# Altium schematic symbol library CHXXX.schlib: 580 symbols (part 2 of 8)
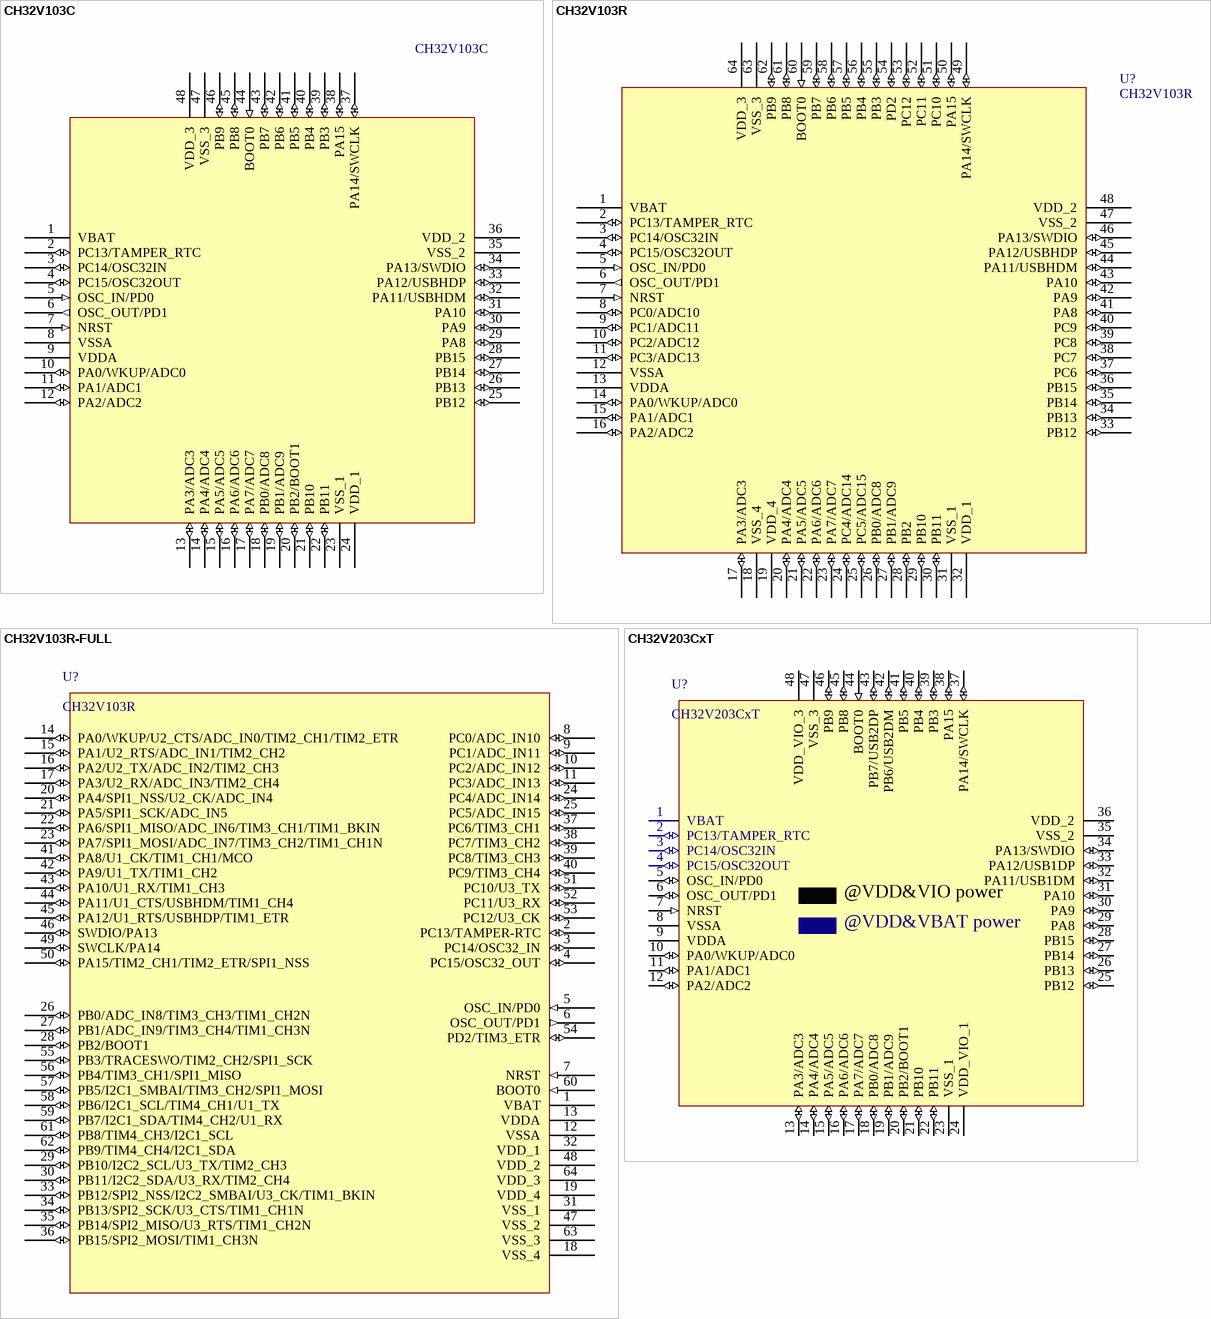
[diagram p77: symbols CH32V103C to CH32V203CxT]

## CH32V103C
designator U?
RISC-V MCU with USB device & USB host & ADC & Touch Key
footprint LQFP48 (Footprint not found)
footprint QFN48_7X7 (Footprint not found)
pins: 1 VBAT (power), 2 PC13/TAMPER_RTC (io), 3 PC14/OSC32IN (io), 4 PC15/OSC32OUT (io), 5 OSC_IN/PD0 (in), 6 OSC_OUT/PD1 (out), 7 NRST (in), 8 VSSA, 9 VDDA, 10 PA0/WKUP/ADC0 (io), 11 PA1/ADC1 (io), 12 PA2/ADC2 (io), 13 PA3/ADC3 (io), 14 PA4/ADC4 (io), 15 PA5/ADC5 (io), 16 PA6/ADC6 (io), 17 PA7/ADC7 (io), 18 PB0/ADC8 (io), 19 PB1/ADC9 (io), 20 PB2/BOOT1 (io), 21 PB10 (io), 22 PB11 (io), 23 VSS_1, 24 VDD_1, 25 PB12 (io), 26 PB13 (io), 27 PB14 (io), 28 PB15 (io), 29 PA8 (io), 30 PA9 (io), 31 PA10 (io), 32 PA11/USBHDM (io), 33 PA12/USBHDP (io), 34 PA13/SWDIO (io), 35 VSS_2, 36 VDD_2, 37 PA14/SWCLK (io), 38 PA15 (io), 39 PB3 (io), 40 PB4 (io), 41 PB5 (io), 42 PB6 (io), 43 PB7 (io), 44 BOOT0 (in), 45 PB8 (io), 46 PB9 (io), 47 VSS_3, 48 VDD_3

## CH32V103R
designator U?
RISC-V MCU with USB device & USB host & ADC & Touch Key
footprint LQFP64M_10X10
pins: 1 VBAT (power), 2 PC13/TAMPER_RTC (io), 3 PC14/OSC32IN (io), 4 PC15/OSC32OUT (io), 5 OSC_IN/PD0 (in), 6 OSC_OUT/PD1 (out), 7 NRST (in), 8 PC0/ADC10 (io), 9 PC1/ADC11 (io), 10 PC2/ADC12 (io), 11 PC3/ADC13 (io), 12 VSSA (power), 13 VDDA (power), 14 PA0/WKUP/ADC0 (io), 15 PA1/ADC1 (io), 16 PA2/ADC2 (io), 17 PA3/ADC3 (io), 18 VSS_4 (power), 19 VDD_4 (power), 20 PA4/ADC4 (io), 21 PA5/ADC5 (io), 22 PA6/ADC6 (io), 23 PA7/ADC7 (io), 24 PC4/ADC14 (io), 25 PC5/ADC15 (io), 26 PB0/ADC8 (io), 27 PB1/ADC9 (io), 28 PB2 (io), 29 PB10 (io), 30 PB11 (io), 31 VSS_1 (power), 32 VDD_1 (power), 33 PB12 (io), 34 PB13 (io), 35 PB14 (io), 36 PB15 (io), 37 PC6 (io), 38 PC7 (io), 39 PC8 (io), 40 PC9 (io), 41 PA8 (io), 42 PA9 (io), 43 PA10 (io), 44 PA11/USBHDM (io), 45 PA12/USBHDP (io), 46 PA13/SWDIO (io), 47 VSS_2 (power), 48 VDD_2 (power), 49 PA14/SWCLK (io), 50 PA15 (io), 51 PC10 (io), 52 PC11 (io), 53 PC12 (io), 54 PD2 (io), 55 PB3 (io), 56 PB4 (io), 57 PB5 (io), 58 PB6 (io), 59 PB7 (io), 60 BOOT0 (in), 61 PB8 (io), 62 PB9 (io), 63 VSS_3 (power), 64 VDD_3 (power)

## CH32V103R-FULL
designator U?, comment CH32V103R
RISC-V MCU with USB device & USB host & ADC & Touch Key
footprint LQFP64M_10X10 (Footprint not found)
pins: 1 VBAT (power), 2 PC13/TAMPER-RTC (io), 3 PC14/OSC32_IN (io), 4 PC15/OSC32_OUT (io), 5 OSC_IN/PD0 (in), 6 OSC_OUT/PD1 (out), 7 NRST (in), 8 PC0/ADC_IN10 (io), 9 PC1/ADC_IN11 (io), 10 PC2/ADC_IN12 (io), 11 PC3/ADC_IN13 (io), 12 VSSA (power), 13 VDDA (power), 14 PA0/WKUP/U2_CTS/ADC_IN0/TIM2_CH1/TIM2_ETR (io), 15 PA1/U2_RTS/ADC_IN1/TIM2_CH2 (io), 16 PA2/U2_TX/ADC_IN2/TIM2_CH3 (io), 17 PA3/U2_RX/ADC_IN3/TIM2_CH4 (io), 18 VSS_4 (power), 19 VDD_4 (power), 20 PA4/SPI1_NSS/U2_CK/ADC_IN4 (io), 21 PA5/SPI1_SCK/ADC_IN5 (io), 22 PA6/SPI1_MISO/ADC_IN6/TIM3_CH1/TIM1_BKIN (io), 23 PA7/SPI1_MOSI/ADC_IN7/TIM3_CH2/TIM1_CH1N (io), 24 PC4/ADC_IN14 (io), 25 PC5/ADC_IN15 (io), 26 PB0/ADC_IN8/TIM3_CH3/TIM1_CH2N (io), 27 PB1/ADC_IN9/TIM3_CH4/TIM1_CH3N (io), 28 PB2/BOOT1 (io), 29 PB10/I2C2_SCL/U3_TX/TIM2_CH3 (io), 30 PB11/I2C2_SDA/U3_RX/TIM2_CH4 (io), 31 VSS_1 (power), 32 VDD_1 (power), 33 PB12/SPI2_NSS/I2C2_SMBAI/U3_CK/TIM1_BKIN (io), 34 PB13/SPI2_SCK/U3_CTS/TIM1_CH1N  (io), 35 PB14/SPI2_MISO/U3_RTS/TIM1_CH2N (io), 36 PB15/SPI2_MOSI/TIM1_CH3N (io), 37 PC6/TIM3_CH1 (io), 38 PC7/TIM3_CH2 (io), 39 PC8/TIM3_CH3 (io), 40 PC9/TIM3_CH4 (io), 41 PA8/U1_CK/TIM1_CH1/MCO (io), 42 PA9/U1_TX/TIM1_CH2 (io), 43 PA10/U1_RX/TIM1_CH3 (io), 44 PA11/U1_CTS/USBHDM/TIM1_CH4 (io), 45 PA12/U1_RTS/USBHDP/TIM1_ETR (io), 46 SWDIO/PA13 (io), 47 VSS_2 (power), 48 VDD_2 (power), 49 SWCLK/PA14 (io), 50 PA15/TIM2_CH1/TIM2_ETR/SPI1_NSS (io), 51 PC10/U3_TX (io), 52 PC11/U3_RX (io), 53 PC12/U3_CK (io), 54 PD2/TIM3_ETR (io), 55 PB3/TRACESWO/TIM2_CH2/SPI1_SCK (io), 56 PB4/TIM3_CH1/SPI1_MISO (io), 57 PB5/I2C1_SMBAI/TIM3_CH2/SPI1_MOSI (io), 58 PB6/I2C1_SCL/TIM4_CH1/U1_TX (io), 59 PB7/I2C1_SDA/TIM4_CH2/U1_RX (io), 60 BOOT0 (in), 61 PB8/TIM4_CH3/I2C1_SCL (io), 62 PB9/TIM4_CH4/I2C1_SDA (io), 63 VSS_3 (power), 64 VDD_3 (power)

## CH32V203CxT
designator U?
RISC-V LMD-MCU, 144MHz, 2*USB FS, CAN
footprint LQFP48
pins: 1 VBAT (power), 2 PC13/TAMPER_RTC (io), 3 PC14/OSC32IN (io), 4 PC15/OSC32OUT (io), 5 OSC_IN/PD0 (io), 6 OSC_OUT/PD1 (io), 7 NRST (in), 8 VSSA (power), 9 VDDA (power), 10 PA0/WKUP/ADC0 (io), 11 PA1/ADC1 (io), 12 PA2/ADC2 (io), 13 PA3/ADC3 (io), 14 PA4/ADC4 (io), 15 PA5/ADC5 (io), 16 PA6/ADC6 (io), 17 PA7/ADC7 (io), 18 PB0/ADC8 (io), 19 PB1/ADC9 (io), 20 PB2/BOOT1 (io), 21 PB10 (io), 22 PB11 (io), 23 VSS_1 (power), 24 VDD_VIO_1 (power), 25 PB12 (io), 26 PB13 (io), 27 PB14 (io), 28 PB15 (io), 29 PA8 (io), 30 PA9 (io), 31 PA10 (io), 32 PA11/USB1DM (io), 33 PA12/USB1DP (io), 34 PA13/SWDIO (io), 35 VSS_2 (power), 36 VDD_2 (power), 37 PA14/SWCLK (io), 38 PA15 (io), 39 PB3 (io), 40 PB4 (io), 41 PB5 (io), 42 PB6/USB2DM (io), 43 PB7/USB2DP (io), 44 BOOT0 (in), 45 PB8 (io), 46 PB9 (io), 47 VSS_3 (power), 48 VDD_VIO_3 (power)

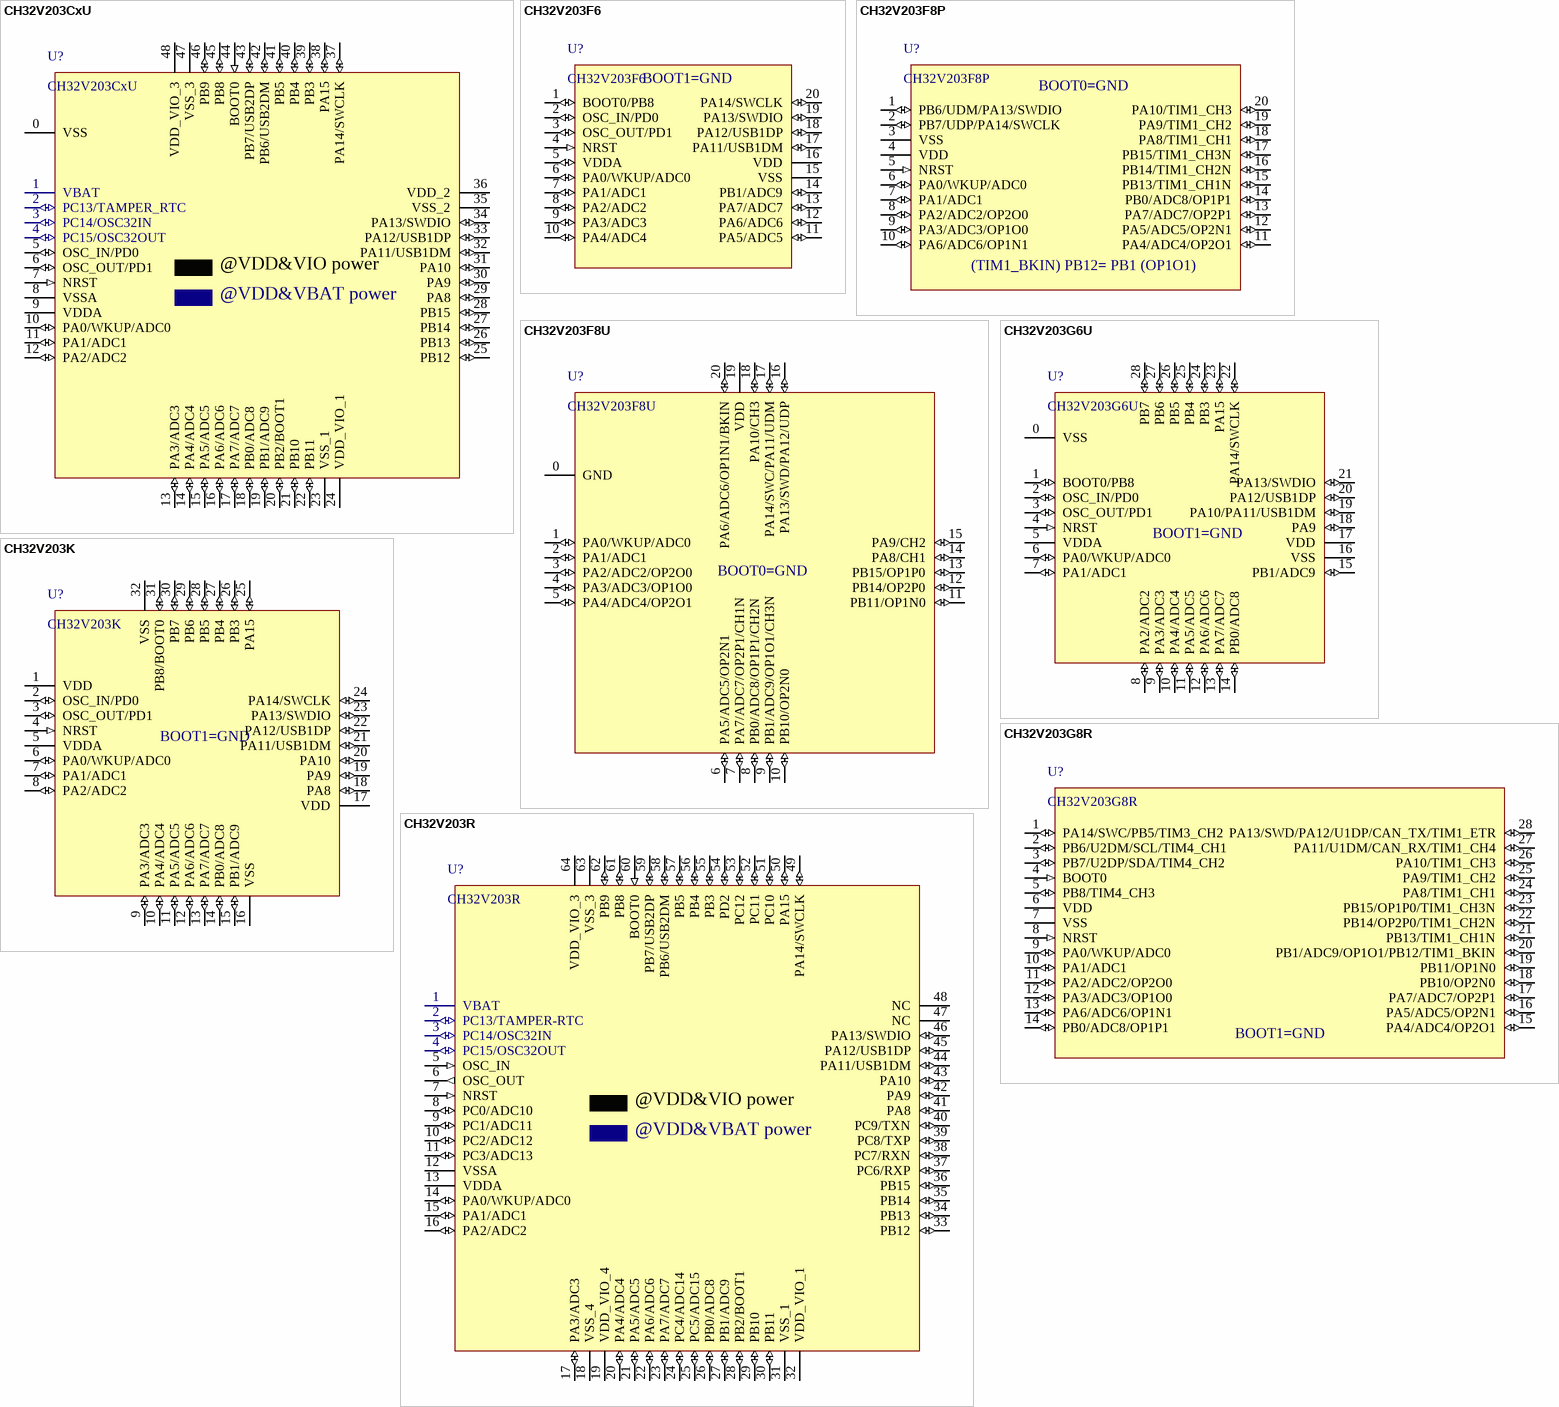
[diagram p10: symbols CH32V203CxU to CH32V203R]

## CH32V203CxU
designator U?
RISC-V LMD-MCU, 144MHz, 2*USB FS, CAN
footprint QFN48_7X7 (Footprint not found)
pins: 0 VSS (power), 1 VBAT (power), 2 PC13/TAMPER_RTC (io), 3 PC14/OSC32IN (io), 4 PC15/OSC32OUT (io), 5 OSC_IN/PD0 (io), 6 OSC_OUT/PD1 (io), 7 NRST (in), 8 VSSA (power), 9 VDDA (power), 10 PA0/WKUP/ADC0 (io), 11 PA1/ADC1 (io), 12 PA2/ADC2 (io), 13 PA3/ADC3 (io), 14 PA4/ADC4 (io), 15 PA5/ADC5 (io), 16 PA6/ADC6 (io), 17 PA7/ADC7 (io), 18 PB0/ADC8 (io), 19 PB1/ADC9 (io), 20 PB2/BOOT1 (io), 21 PB10 (io), 22 PB11 (io), 23 VSS_1 (power), 24 VDD_VIO_1 (power), 25 PB12 (io), 26 PB13 (io), 27 PB14 (io), 28 PB15 (io), 29 PA8 (io), 30 PA9 (io), 31 PA10 (io), 32 PA11/USB1DM (io), 33 PA12/USB1DP (io), 34 PA13/SWDIO (io), 35 VSS_2 (power), 36 VDD_2 (power), 37 PA14/SWCLK (io), 38 PA15 (io), 39 PB3 (io), 40 PB4 (io), 41 PB5 (io), 42 PB6/USB2DM (io), 43 PB7/USB2DP (io), 44 BOOT0 (in), 45 PB8 (io), 46 PB9 (io), 47 VSS_3 (power), 48 VDD_VIO_3 (power)

## CH32V203F6
designator U?
RISC-V LMD-MCU, 144MHz, USB FS, CAN, Mul-ADC,OPA
footprint TSSOP20
pins: 1 BOOT0/PB8 (io), 2 OSC_IN/PD0 (io), 3 OSC_OUT/PD1 (io), 4 NRST (in), 5 VDDA (io), 6 PA0/WKUP/ADC0 (io), 7 PA1/ADC1 (io), 8 PA2/ADC2 (io), 9 PA3/ADC3 (io), 10 PA4/ADC4 (io), 11 PA5/ADC5 (io), 12 PA6/ADC6 (io), 13 PA7/ADC7 (io), 14 PB1/ADC9 (io), 15 VSS (power), 16 VDD (power), 17 PA11/USB1DM (io), 18 PA12/USB1DP (io), 19 PA13/SWDIO (io), 20 PA14/SWCLK (io)

## CH32V203F8P
designator U?
RISC-V LMD-MCU, 144MHz, for motor
footprint TSSOP20
pins: 1 PB6/UDM/PA13/SWDIO (io), 2 PB7/UDP/PA14/SWCLK (io), 3 VSS (power), 4 VDD (power), 5 NRST (in), 6 PA0/WKUP/ADC0 (io), 7 PA1/ADC1 (io), 8 PA2/ADC2/OP2O0 (io), 9 PA3/ADC3/OP1O0 (io), 10 PA6/ADC6/OP1N1 (io), 11 PA4/ADC4/OP2O1 (io), 12 PA5/ADC5/OP2N1 (io), 13 PA7/ADC7/OP2P1 (io), 14 PB0/ADC8/OP1P1 (io), 15 PB13/TIM1_CH1N (io), 16 PB14/TIM1_CH2N (io), 17 PB15/TIM1_CH3N (io), 18 PA8/TIM1_CH1 (io), 19 PA9/TIM1_CH2 (io), 20 PA10/TIM1_CH3 (io)

## CH32V203F8U
designator U?
RISC-V LMD-MCU, 144MHz, for motor & wireless charging
footprint QFN20_3X3
pins: 0 GND (power), 1 PA0/WKUP/ADC0 (io), 2 PA1/ADC1 (io), 3 PA2/ADC2/OP2O0 (io), 4 PA3/ADC3/OP1O0 (io), 5 PA4/ADC4/OP2O1 (io), 6 PA5/ADC5/OP2N1 (io), 7 PA7/ADC7/OP2P1/CH1N (io), 8 PB0/ADC8/OP1P1/CH2N (io), 9 PB1/ADC9/OP1O1/CH3N (io), 10 PB10/OP2N0 (io), 11 PB11/OP1N0 (io), 12 PB14/OP2P0 (io), 13 PB15/OP1P0 (io), 14 PA8/CH1 (io), 15 PA9/CH2 (io), 16 PA13/SWD/PA12/UDP (io), 17 PA14/SWC/PA11/UDM (io), 18 PA10/CH3 (io), 19 VDD (power), 20 PA6/ADC6/OP1N1/BKIN (io)

## CH32V203G6U
designator U?
RISC-V LMD-MCU, 144MHz, USB FS, CAN, Mul-ADC,OPA
footprint QFN28_4X4
pins: 0 VSS (power), 1 BOOT0/PB8 (io), 2 OSC_IN/PD0 (io), 3 OSC_OUT/PD1 (io), 4 NRST (in), 5 VDDA (power), 6 PA0/WKUP/ADC0 (io), 7 PA1/ADC1 (io), 8 PA2/ADC2 (io), 9 PA3/ADC3 (io), 10 PA4/ADC4 (io), 11 PA5/ADC5 (io), 12 PA6/ADC6 (io), 13 PA7/ADC7 (io), 14 PB0/ADC8 (io), 15 PB1/ADC9 (io), 16 VSS (power), 17 VDD (power), 18 PA9 (io), 19 PA10/PA11/USB1DM (io), 20 PA12/USB1DP (io), 21 PA13/SWDIO (io), 22 PA14/SWCLK (io), 23 PA15 (io), 24 PB3 (io), 25 PB4 (io), 26 PB5 (io), 27 PB6 (io), 28 PB7 (io)

## CH32V203G8R
designator U?
RISC-V LMD-MCU, 144MHz, for motor & wireless charging
footprint QSOP28
pins: 1 PA14/SWC/PB5/TIM3_CH2 (io), 2 PB6/U2DM/SCL/TIM4_CH1 (io), 3 PB7/U2DP/SDA/TIM4_CH2 (io), 4 BOOT0 (in), 5 PB8/TIM4_CH3 (io), 6 VDD (power), 7 VSS (power), 8 NRST (in), 9 PA0/WKUP/ADC0 (io), 10 PA1/ADC1 (io), 11 PA2/ADC2/OP2O0 (io), 12 PA3/ADC3/OP1O0 (io), 13 PA6/ADC6/OP1N1 (io), 14 PB0/ADC8/OP1P1 (io), 15 PA4/ADC4/OP2O1 (io), 16 PA5/ADC5/OP2N1 (io), 17 PA7/ADC7/OP2P1 (io), 18 PB10/OP2N0 (io), 19 PB11/OP1N0 (io), 20 PB1/ADC9/OP1O1/PB12/TIM1_BKIN (io), 21 PB13/TIM1_CH1N (io), 22 PB14/OP2P0/TIM1_CH2N (io), 23 PB15/OP1P0/TIM1_CH3N (io), 24 PA8/TIM1_CH1 (io), 25 PA9/TIM1_CH2 (io), 26 PA10/TIM1_CH3 (io), 27 PA11/U1DM/CAN_RX/TIM1_CH4 (io), 28 PA13/SWD/PA12/U1DP/CAN_TX/TIM1_ETR (io)

## CH32V203K
designator U?
RISC-V LMD-MCU, 144MHz, USB FS, CAN
footprint LQFP32
pins: 1 VDD (power), 2 OSC_IN/PD0 (io), 3 OSC_OUT/PD1 (io), 4 NRST (in), 5 VDDA (power), 6 PA0/WKUP/ADC0 (io), 7 PA1/ADC1 (io), 8 PA2/ADC2 (io), 9 PA3/ADC3 (io), 10 PA4/ADC4 (io), 11 PA5/ADC5 (io), 12 PA6/ADC6 (io), 13 PA7/ADC7 (io), 14 PB0/ADC8 (io), 15 PB1/ADC9 (io), 16 VSS (power), 17 VDD (power), 18 PA8 (io), 19 PA9 (io), 20 PA10 (io), 21 PA11/USB1DM (io), 22 PA12/USB1DP (io), 23 PA13/SWDIO (io), 24 PA14/SWCLK (io), 25 PA15 (io), 26 PB3 (io), 27 PB4 (io), 28 PB5 (io), 29 PB6 (io), 30 PB7 (io), 31 PB8/BOOT0 (io), 32 VSS (power)

## CH32V203R
designator U?
RISC-V HD-MCU, 10M Ethernet, 2*USB, CAN
footprint LQFP64M_10X10
pins: 1 VBAT (power), 2 PC13/TAMPER-RTC (io), 3 PC14/OSC32IN (io), 4 PC15/OSC32OUT (io), 5 OSC_IN (in), 6 OSC_OUT (out), 7 NRST (in), 8 PC0/ADC10 (io), 9 PC1/ADC11 (io), 10 PC2/ADC12 (io), 11 PC3/ADC13 (io), 12 VSSA (power), 13 VDDA (power), 14 PA0/WKUP/ADC0 (io), 15 PA1/ADC1 (io), 16 PA2/ADC2 (io), 17 PA3/ADC3 (io), 18 VSS_4 (power), 19 VDD_VIO_4 (power), 20 PA4/ADC4 (io), 21 PA5/ADC5 (io), 22 PA6/ADC6 (io), 23 PA7/ADC7 (io), 24 PC4/ADC14 (io), 25 PC5/ADC15 (io), 26 PB0/ADC8 (io), 27 PB1/ADC9 (io), 28 PB2/BOOT1 (io), 29 PB10 (io), 30 PB11 (io), 31 VSS_1 (power), 32 VDD_VIO_1 (power), 33 PB12 (io), 34 PB13 (io), 35 PB14 (io), 36 PB15 (io), 37 PC6/RXP (io), 38 PC7/RXN (io), 39 PC8/TXP (io), 40 PC9/TXN (io), 41 PA8 (io), 42 PA9 (io), 43 PA10 (io), 44 PA11/USB1DM (io), 45 PA12/USB1DP (io), 46 PA13/SWDIO (io), 47 NC (power), 48 NC (power), 49 PA14/SWCLK (io), 50 PA15 (io), 51 PC10 (io), 52 PC11 (io), 53 PC12 (io), 54 PD2 (io), 55 PB3 (io), 56 PB4 (io), 57 PB5 (io), 58 PB6/USB2DM (io), 59 PB7/USB2DP (io), 60 BOOT0 (in), 61 PB8 (io), 62 PB9 (io), 63 VSS_3 (power), 64 VDD_VIO_3 (power)

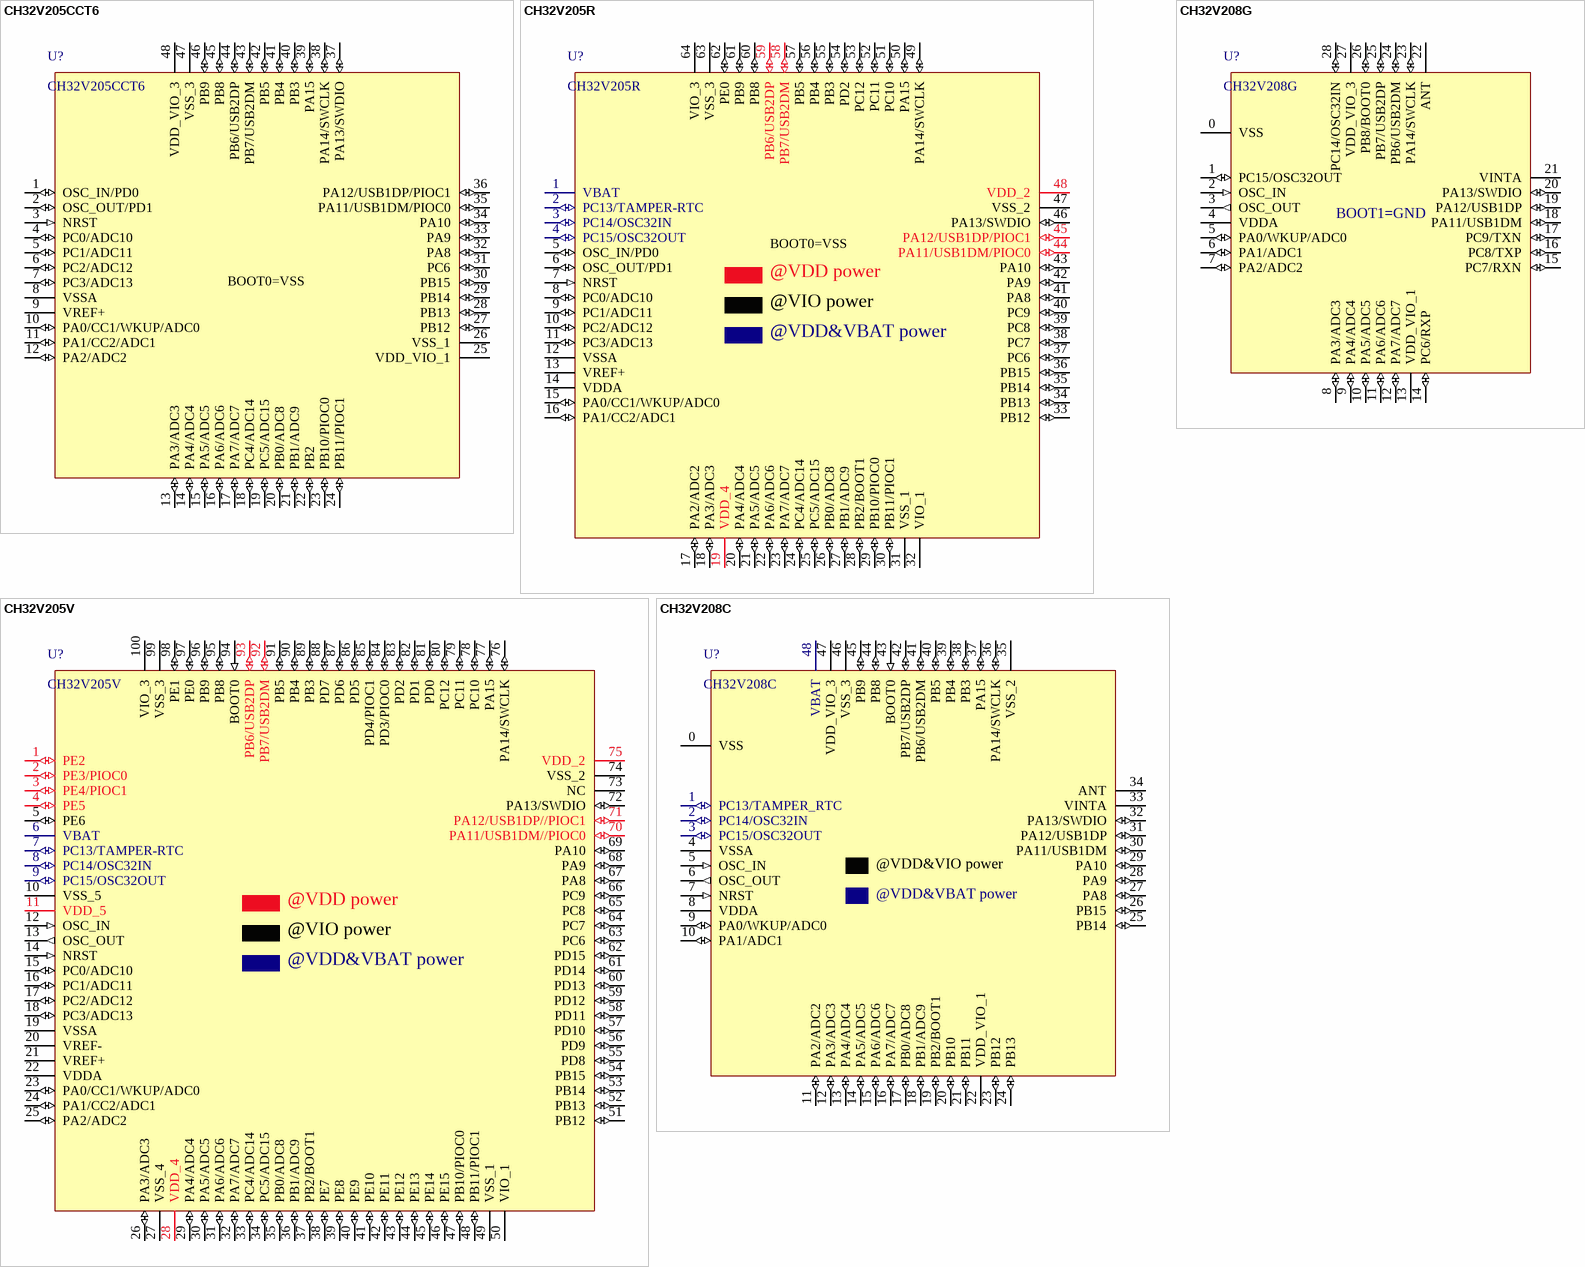
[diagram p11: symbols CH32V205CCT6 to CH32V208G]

## CH32V205CCT6
designator U?
RISC-V MCU, 192MHz, USB_480M, USB FS, PD, PIOC, ADC, TKEY, 2*OPA, 2*CMP
footprint LQFP48
pins: 1 OSC_IN/PD0 (io), 2 OSC_OUT/PD1 (io), 3 NRST (in), 4 PC0/ADC10 (io), 5 PC1/ADC11 (io), 6 PC2/ADC12 (io), 7 PC3/ADC13 (io), 8 VSSA (power), 9 VREF+ (power), 10 PA0/CC1/WKUP/ADC0 (io), 11 PA1/CC2/ADC1 (io), 12 PA2/ADC2 (io), 13 PA3/ADC3 (io), 14 PA4/ADC4 (io), 15 PA5/ADC5 (io), 16 PA6/ADC6 (io), 17 PA7/ADC7 (io), 18 PC4/ADC14 (io), 19 PC5/ADC15 (io), 20 PB0/ADC8 (io), 21 PB1/ADC9 (io), 22 PB2 (io), 23 PB10/PIOC0 (io), 24 PB11/PIOC1 (io), 25 VDD_VIO_1 (power), 26 VSS_1 (power), 27 PB12 (io), 28 PB13 (io), 29 PB14 (io), 30 PB15 (io), 31 PC6 (io), 32 PA8 (io), 33 PA9 (io), 34 PA10 (io), 35 PA11/USB1DM/PIOC0 (io), 36 PA12/USB1DP/PIOC1 (io), 37 PA13/SWDIO (io), 38 PA14/SWCLK (io), 39 PA15 (io), 40 PB3 (io), 41 PB4 (io), 42 PB5 (io), 43 PB7/USB2DM (io), 44 PB6/USB2DP (io), 45 PB8 (io), 46 PB9 (io), 47 VSS_3 (power), 48 VDD_VIO_3 (power)

## CH32V205R
designator U?
RISC-V MCU, 192MHz, USB_480M, USB FS, PD, PIOC, ADC, TKEY, 2*OPA, 2*CMP
footprint LQFP64_7X7 (Footprint not found)
pins: 1 VBAT (power), 2 PC13/TAMPER-RTC (io), 3 PC14/OSC32IN (io), 4 PC15/OSC32OUT (io), 5 OSC_IN/PD0 (io), 6 OSC_OUT/PD1 (io), 7 NRST (in), 8 PC0/ADC10 (io), 9 PC1/ADC11 (io), 10 PC2/ADC12 (io), 11 PC3/ADC13 (io), 12 VSSA (power), 13 VREF+ (power), 14 VDDA (power), 15 PA0/CC1/WKUP/ADC0 (io), 16 PA1/CC2/ADC1 (io), 17 PA2/ADC2 (io), 18 PA3/ADC3 (io), 19 VDD_4 (power), 20 PA4/ADC4 (io), 21 PA5/ADC5 (io), 22 PA6/ADC6 (io), 23 PA7/ADC7 (io), 24 PC4/ADC14 (io), 25 PC5/ADC15 (io), 26 PB0/ADC8 (io), 27 PB1/ADC9 (io), 28 PB2/BOOT1 (io), 29 PB10/PIOC0 (io), 30 PB11/PIOC1 (io), 31 VSS_1 (power), 32 VIO_1 (power), 33 PB12 (io), 34 PB13 (io), 35 PB14 (io), 36 PB15 (io), 37 PC6 (io), 38 PC7 (io), 39 PC8 (io), 40 PC9 (io), 41 PA8 (io), 42 PA9 (io), 43 PA10 (io), 44 PA11/USB1DM/PIOC0 (io), 45 PA12/USB1DP/PIOC1 (io), 46 PA13/SWDIO (io), 47 VSS_2 (power), 48 VDD_2 (power), 49 PA14/SWCLK (io), 50 PA15 (io), 51 PC10 (io), 52 PC11 (io), 53 PC12 (io), 54 PD2 (io), 55 PB3 (io), 56 PB4 (io), 57 PB5 (io), 58 PB7/USB2DM (io), 59 PB6/USB2DP (io), 60 PB8 (io), 61 PB9 (io), 62 PE0 (io), 63 VSS_3 (power), 64 VIO_3 (power)

## CH32V205V
designator U?
RISC-V MCU, 192MHz, USB_480M, USB FS, PD, PIOC, ADC, TKEY, 2*OPA, 2*CMP
footprint LQFP100
pins: 1 PE2 (io), 2 PE3/PIOC0 (io), 3 PE4/PIOC1 (io), 4 PE5 (io), 5 PE6 (io), 6 VBAT (power), 7 PC13/TAMPER-RTC (io), 8 PC14/OSC32IN (io), 9 PC15/OSC32OUT (io), 10 VSS_5 (power), 11 VDD_5 (power), 12 OSC_IN (in), 13 OSC_OUT (out), 14 NRST (in), 15 PC0/ADC10 (io), 16 PC1/ADC11 (io), 17 PC2/ADC12 (io), 18 PC3/ADC13 (io), 19 VSSA (power), 20 VREF- (power), 21 VREF+ (power), 22 VDDA (power), 23 PA0/CC1/WKUP/ADC0 (io), 24 PA1/CC2/ADC1 (io), 25 PA2/ADC2 (io), 26 PA3/ADC3 (io), 27 VSS_4 (power), 28 VDD_4 (power), 29 PA4/ADC4 (io), 30 PA5/ADC5 (io), 31 PA6/ADC6 (io), 32 PA7/ADC7 (io), 33 PC4/ADC14 (io), 34 PC5/ADC15 (io), 35 PB0/ADC8 (io), 36 PB1/ADC9 (io), 37 PB2/BOOT1 (io), 38 PE7 (io), 39 PE8 (io), 40 PE9 (io), 41 PE10 (io), 42 PE11 (io), 43 PE12 (io), 44 PE13 (io), 45 PE14 (io), 46 PE15 (io), 47 PB10/PIOC0 (io), 48 PB11/PIOC1 (io), 49 VSS_1 (power), 50 VIO_1 (power), 51 PB12 (io), 52 PB13 (io), 53 PB14 (io), 54 PB15 (io), 55 PD8 (io), 56 PD9 (io), 57 PD10 (io), 58 PD11 (io), 59 PD12 (io), 60 PD13 (io), 61 PD14 (io), 62 PD15 (io), 63 PC6 (io), 64 PC7 (io), 65 PC8 (io), 66 PC9 (io), 67 PA8 (io), 68 PA9 (io), 69 PA10 (io), 70 PA11/USB1DM//PIOC0 (io), 71 PA12/USB1DP//PIOC1 (io), 72 PA13/SWDIO (io), 73 NC (hiz), 74 VSS_2 (power), 75 VDD_2 (power), 76 PA14/SWCLK (io), 77 PA15 (io), 78 PC10 (io), 79 PC11 (io), 80 PC12 (io), 81 PD0 (io), 82 PD1 (io), 83 PD2 (io), 84 PD3/PIOC0 (io), 85 PD4/PIOC1 (io), 86 PD5 (io), 87 PD6 (io), 88 PD7 (io), 89 PB3 (io), 90 PB4 (io), 91 PB5 (io), 92 PB7/USB2DM (io), 93 PB6/USB2DP (io), 94 BOOT0 (in), 95 PB8 (io), 96 PB9 (io), 97 PE0 (io), 98 PE1 (io), 99 VSS_3 (power), 100 VIO_3 (power)

## CH32V208C
designator U?
RISC-V BLE5.3 MCU, 10M Ethernet, 2*USB, CAN
footprint QFN48_5X5
pins: 0 VSS (power), 1 PC13/TAMPER_RTC (io), 2 PC14/OSC32IN (io), 3 PC15/OSC32OUT (io), 4 VSSA (power), 5 OSC_IN (in), 6 OSC_OUT (out), 7 NRST (in), 8 VDDA (power), 9 PA0/WKUP/ADC0 (io), 10 PA1/ADC1 (io), 11 PA2/ADC2 (io), 12 PA3/ADC3 (io), 13 PA4/ADC4 (io), 14 PA5/ADC5 (io), 15 PA6/ADC6 (io), 16 PA7/ADC7 (io), 17 PB0/ADC8 (io), 18 PB1/ADC9 (io), 19 PB2/BOOT1 (io), 20 PB10 (io), 21 PB11 (io), 22 VDD_VIO_1 (power), 23 PB12 (io), 24 PB13 (io), 25 PB14 (io), 26 PB15 (io), 27 PA8 (io), 28 PA9 (io), 29 PA10 (io), 30 PA11/USB1DM (io), 31 PA12/USB1DP (io), 32 PA13/SWDIO (io), 33 VINTA (power), 34 ANT (power), 35 VSS_2 (power), 36 PA14/SWCLK (io), 37 PA15 (io), 38 PB3 (io), 39 PB4 (io), 40 PB5 (io), 41 PB6/USB2DM (io), 42 PB7/USB2DP (io), 43 BOOT0 (in), 44 PB8 (io), 45 PB9 (io), 46 VSS_3 (power), 47 VDD_VIO_3 (power), 48 VBAT (power)

## CH32V208G
designator U?
RISC-V BLE5.3 MCU, 10M Ethernet, 2*USB, CAN
footprint QFN28_4X4
pins: 0 VSS (power), 1 PC15/OSC32OUT (io), 2 OSC_IN (in), 3 OSC_OUT (out), 4 VDDA (power), 5 PA0/WKUP/ADC0 (io), 6 PA1/ADC1 (io), 7 PA2/ADC2 (io), 8 PA3/ADC3 (io), 9 PA4/ADC4 (io), 10 PA5/ADC5 (io), 11 PA6/ADC6 (io), 12 PA7/ADC7 (io), 13 VDD_VIO_1 (power), 14 PC6/RXP (io), 15 PC7/RXN (io), 16 PC8/TXP (io), 17 PC9/TXN (io), 18 PA11/USB1DM (io), 19 PA12/USB1DP (io), 20 PA13/SWDIO (io), 21 VINTA (power), 22 ANT (power), 23 PA14/SWCLK (io), 24 PB6/USB2DM (io), 25 PB7/USB2DP (io), 26 PB8/BOOT0 (io), 27 VDD_VIO_3 (power), 28 PC14/OSC32IN (io)

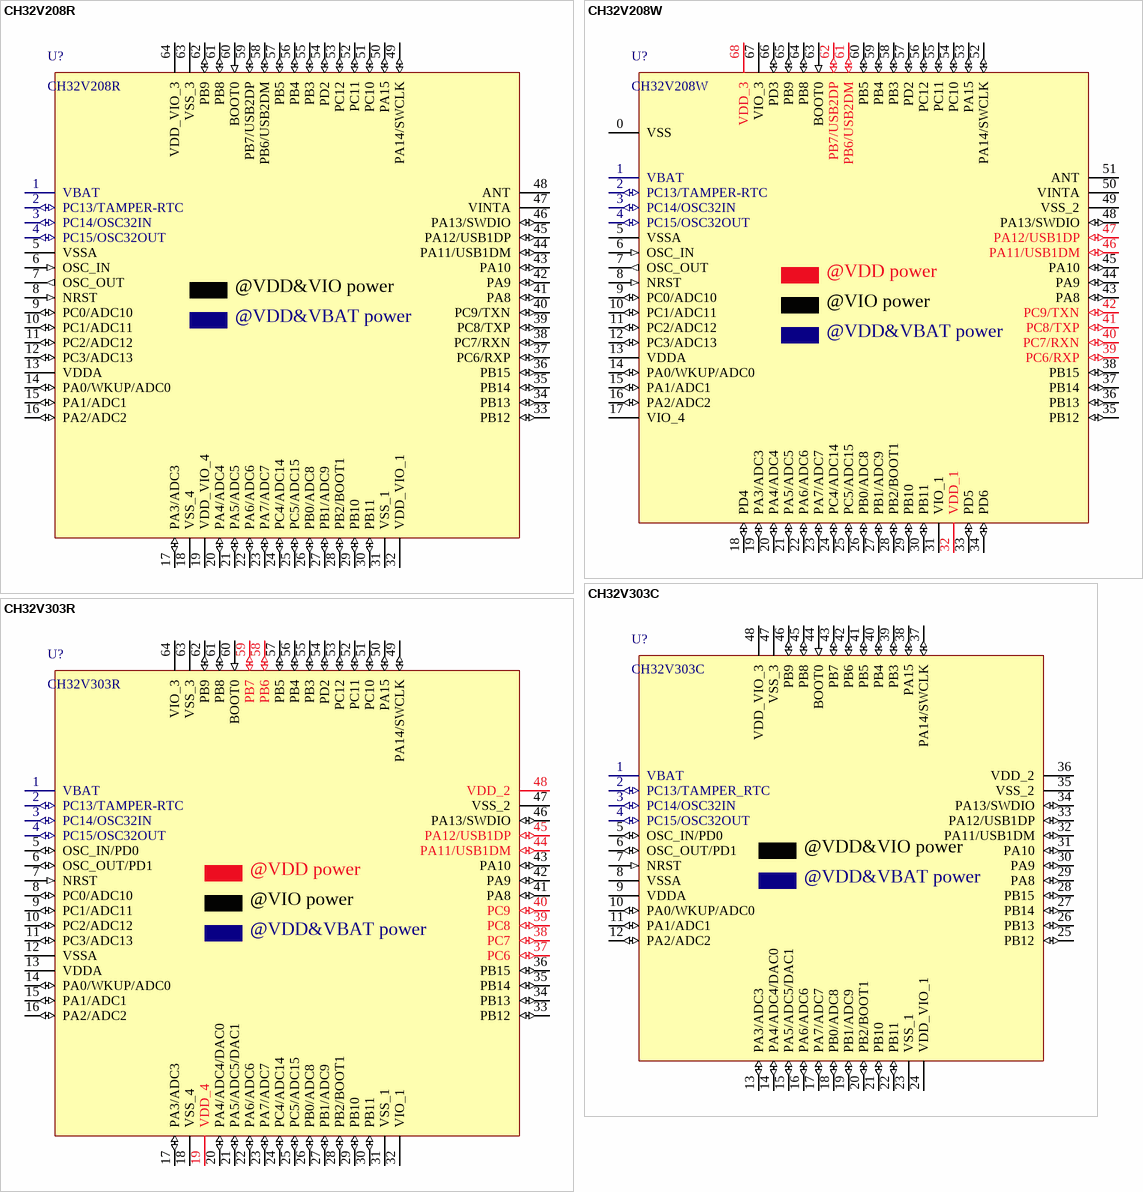
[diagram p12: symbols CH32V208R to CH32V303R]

## CH32V208R
designator U?
RISC-V BLE5.3 MCU, 10M Ethernet, 2*USB, CAN
footprint LQFP64M_10X10
pins: 1 VBAT (power), 2 PC13/TAMPER-RTC (io), 3 PC14/OSC32IN (io), 4 PC15/OSC32OUT (io), 5 VSSA (power), 6 OSC_IN (in), 7 OSC_OUT (out), 8 NRST (in), 9 PC0/ADC10 (io), 10 PC1/ADC11 (io), 11 PC2/ADC12 (io), 12 PC3/ADC13 (io), 13 VDDA (power), 14 PA0/WKUP/ADC0 (io), 15 PA1/ADC1 (io), 16 PA2/ADC2 (io), 17 PA3/ADC3 (io), 18 VSS_4 (power), 19 VDD_VIO_4 (power), 20 PA4/ADC4 (io), 21 PA5/ADC5 (io), 22 PA6/ADC6 (io), 23 PA7/ADC7 (io), 24 PC4/ADC14 (io), 25 PC5/ADC15 (io), 26 PB0/ADC8 (io), 27 PB1/ADC9 (io), 28 PB2/BOOT1 (io), 29 PB10 (io), 30 PB11 (io), 31 VSS_1 (power), 32 VDD_VIO_1 (power), 33 PB12 (io), 34 PB13 (io), 35 PB14 (io), 36 PB15 (io), 37 PC6/RXP (io), 38 PC7/RXN (io), 39 PC8/TXP (io), 40 PC9/TXN (io), 41 PA8 (io), 42 PA9 (io), 43 PA10 (io), 44 PA11/USB1DM (io), 45 PA12/USB1DP (io), 46 PA13/SWDIO (io), 47 VINTA (power), 48 ANT (power), 49 PA14/SWCLK (io), 50 PA15 (io), 51 PC10 (io), 52 PC11 (io), 53 PC12 (io), 54 PD2 (io), 55 PB3 (io), 56 PB4 (io), 57 PB5 (io), 58 PB6/USB2DM (io), 59 PB7/USB2DP (io), 60 BOOT0 (in), 61 PB8 (io), 62 PB9 (io), 63 VSS_3 (power), 64 VDD_VIO_3 (power)

## CH32V208W
designator U?
RISC-V BLE5.3 MCU, 10M Ethernet, 2*USB, CAN
footprint QFN68_8X8
pins: 0 VSS (power), 1 VBAT (power), 2 PC13/TAMPER-RTC (io), 3 PC14/OSC32IN (io), 4 PC15/OSC32OUT (io), 5 VSSA (power), 6 OSC_IN (in), 7 OSC_OUT (out), 8 NRST (in), 9 PC0/ADC10 (io), 10 PC1/ADC11 (io), 11 PC2/ADC12 (io), 12 PC3/ADC13 (io), 13 VDDA (power), 14 PA0/WKUP/ADC0 (io), 15 PA1/ADC1 (io), 16 PA2/ADC2 (io), 17 VIO_4 (power), 18 PD4 (io), 19 PA3/ADC3 (io), 20 PA4/ADC4 (io), 21 PA5/ADC5 (io), 22 PA6/ADC6 (io), 23 PA7/ADC7 (io), 24 PC4/ADC14 (io), 25 PC5/ADC15 (io), 26 PB0/ADC8 (io), 27 PB1/ADC9 (io), 28 PB2/BOOT1 (io), 29 PB10 (io), 30 PB11 (io), 31 VIO_1 (power), 32 VDD_1 (power), 33 PD5 (io), 34 PD6 (io), 35 PB12 (io), 36 PB13 (io), 37 PB14 (io), 38 PB15 (io), 39 PC6/RXP (io), 40 PC7/RXN (io), 41 PC8/TXP (io), 42 PC9/TXN (io), 43 PA8 (io), 44 PA9 (io), 45 PA10 (io), 46 PA11/USB1DM (io), 47 PA12/USB1DP (io), 48 PA13/SWDIO (io), 49 VSS_2 (power), 50 VINTA (power), 51 ANT (power), 52 PA14/SWCLK (io), 53 PA15 (io), 54 PC10 (io), 55 PC11 (io), 56 PC12 (io), 57 PD2 (io), 58 PB3 (io), 59 PB4 (io), 60 PB5 (io), 61 PB6/USB2DM (io), 62 PB7/USB2DP (io), 63 BOOT0 (in), 64 PB8 (io), 65 PB9 (io), 66 PD3 (io), 67 VIO_3 (power), 68 VDD_3 (power)

## CH32V303C
designator U?
RISC-V FPU HD-MCU, 144MHz, 8*UART, 10*Timer, 4*OPA
footprint LQFP48
pins: 1 VBAT (power), 2 PC13/TAMPER_RTC (io), 3 PC14/OSC32IN (io), 4 PC15/OSC32OUT (io), 5 OSC_IN/PD0 (io), 6 OSC_OUT/PD1 (io), 7 NRST (in), 8 VSSA (power), 9 VDDA (power), 10 PA0/WKUP/ADC0 (io), 11 PA1/ADC1 (io), 12 PA2/ADC2 (io), 13 PA3/ADC3 (io), 14 PA4/ADC4/DAC0 (io), 15 PA5/ADC5/DAC1 (io), 16 PA6/ADC6 (io), 17 PA7/ADC7 (io), 18 PB0/ADC8 (io), 19 PB1/ADC9 (io), 20 PB2/BOOT1 (io), 21 PB10 (io), 22 PB11 (io), 23 VSS_1 (power), 24 VDD_VIO_1 (power), 25 PB12 (io), 26 PB13 (io), 27 PB14 (io), 28 PB15 (io), 29 PA8 (io), 30 PA9 (io), 31 PA10 (io), 32 PA11/USB1DM (io), 33 PA12/USB1DP (io), 34 PA13/SWDIO (io), 35 VSS_2 (power), 36 VDD_2 (power), 37 PA14/SWCLK (io), 38 PA15 (io), 39 PB3 (io), 40 PB4 (io), 41 PB5 (io), 42 PB6 (io), 43 PB7 (io), 44 BOOT0 (in), 45 PB8 (io), 46 PB9 (io), 47 VSS_3 (power), 48 VDD_VIO_3 (power)

## CH32V303R
designator U?
RISC-V FPU HD-MCU, 144MHz, 8*UART, 10*Timer, 4*OPA
footprint LQFP64M_10X10
pins: 1 VBAT (power), 2 PC13/TAMPER-RTC (io), 3 PC14/OSC32IN (io), 4 PC15/OSC32OUT (io), 5 OSC_IN/PD0 (io), 6 OSC_OUT/PD1 (io), 7 NRST (in), 8 PC0/ADC10 (io), 9 PC1/ADC11 (io), 10 PC2/ADC12 (io), 11 PC3/ADC13 (io), 12 VSSA (power), 13 VDDA (power), 14 PA0/WKUP/ADC0 (io), 15 PA1/ADC1 (io), 16 PA2/ADC2 (io), 17 PA3/ADC3 (io), 18 VSS_4 (power), 19 VDD_4 (power), 20 PA4/ADC4/DAC0 (io), 21 PA5/ADC5/DAC1 (io), 22 PA6/ADC6 (io), 23 PA7/ADC7 (io), 24 PC4/ADC14 (io), 25 PC5/ADC15 (io), 26 PB0/ADC8 (io), 27 PB1/ADC9 (io), 28 PB2/BOOT1 (io), 29 PB10 (io), 30 PB11 (io), 31 VSS_1 (power), 32 VIO_1 (power), 33 PB12 (io), 34 PB13 (io), 35 PB14 (io), 36 PB15 (io), 37 PC6 (io), 38 PC7 (io), 39 PC8 (io), 40 PC9 (io), 41 PA8 (io), 42 PA9 (io), 43 PA10 (io), 44 PA11/USB1DM (io), 45 PA12/USB1DP (io), 46 PA13/SWDIO (io), 47 VSS_2 (power), 48 VDD_2 (power), 49 PA14/SWCLK (io), 50 PA15 (io), 51 PC10 (io), 52 PC11 (io), 53 PC12 (io), 54 PD2 (io), 55 PB3 (io), 56 PB4 (io), 57 PB5 (io), 58 PB6 (io), 59 PB7 (io), 60 BOOT0 (in), 61 PB8 (io), 62 PB9 (io), 63 VSS_3 (power), 64 VIO_3 (power)

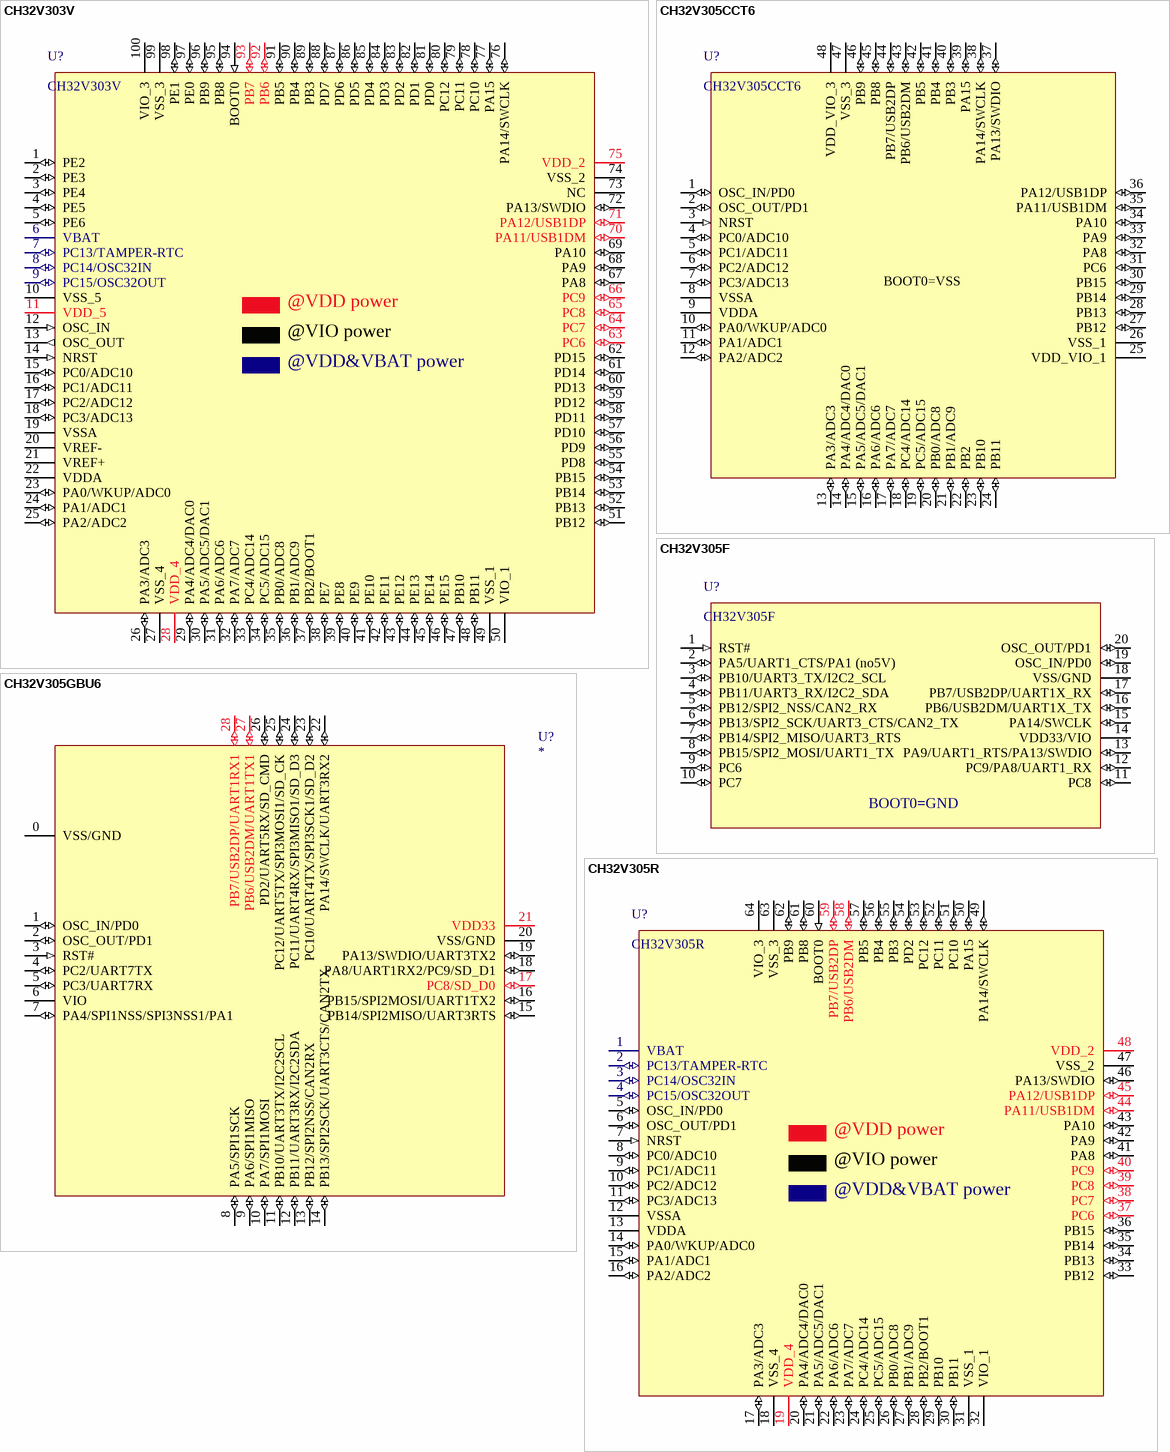
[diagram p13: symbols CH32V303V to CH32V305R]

## CH32V303V
designator U?
RISC-V FPU HD-MCU, 144MHz, 8*UART, 10*Timer, 4*OPA
footprint LQFP100
pins: 1 PE2 (io), 2 PE3 (io), 3 PE4 (io), 4 PE5 (io), 5 PE6 (io), 6 VBAT (power), 7 PC13/TAMPER-RTC (io), 8 PC14/OSC32IN (io), 9 PC15/OSC32OUT (io), 10 VSS_5 (power), 11 VDD_5 (power), 12 OSC_IN (in), 13 OSC_OUT (out), 14 NRST (in), 15 PC0/ADC10 (io), 16 PC1/ADC11 (io), 17 PC2/ADC12 (io), 18 PC3/ADC13 (io), 19 VSSA (power), 20 VREF- (power), 21 VREF+ (power), 22 VDDA (power), 23 PA0/WKUP/ADC0 (io), 24 PA1/ADC1 (io), 25 PA2/ADC2 (io), 26 PA3/ADC3 (io), 27 VSS_4 (power), 28 VDD_4 (power), 29 PA4/ADC4/DAC0 (io), 30 PA5/ADC5/DAC1 (io), 31 PA6/ADC6 (io), 32 PA7/ADC7 (io), 33 PC4/ADC14 (io), 34 PC5/ADC15 (io), 35 PB0/ADC8 (io), 36 PB1/ADC9 (io), 37 PB2/BOOT1 (io), 38 PE7 (io), 39 PE8 (io), 40 PE9 (io), 41 PE10 (io), 42 PE11 (io), 43 PE12 (io), 44 PE13 (io), 45 PE14 (io), 46 PE15 (io), 47 PB10 (io), 48 PB11 (io), 49 VSS_1 (power), 50 VIO_1 (power), 51 PB12 (io), 52 PB13 (io), 53 PB14 (io), 54 PB15 (io), 55 PD8 (io), 56 PD9 (io), 57 PD10 (io), 58 PD11 (io), 59 PD12 (io), 60 PD13 (io), 61 PD14 (io), 62 PD15 (io), 63 PC6 (io), 64 PC7 (io), 65 PC8 (io), 66 PC9 (io), 67 PA8 (io), 68 PA9 (io), 69 PA10 (io), 70 PA11/USB1DM (io), 71 PA12/USB1DP (io), 72 PA13/SWDIO (io), 73 NC (hiz), 74 VSS_2 (power), 75 VDD_2 (power), 76 PA14/SWCLK (io), 77 PA15 (io), 78 PC10 (io), 79 PC11 (io), 80 PC12 (io), 81 PD0 (io), 82 PD1 (io), 83 PD2 (io), 84 PD3 (io), 85 PD4 (io), 86 PD5 (io), 87 PD6 (io), 88 PD7 (io), 89 PB3 (io), 90 PB4 (io), 91 PB5 (io), 92 PB6 (io), 93 PB7 (io), 94 BOOT0 (in), 95 PB8 (io), 96 PB9 (io), 97 PE0 (io), 98 PE1 (io), 99 VSS_3 (power), 100 VIO_3 (power)

## CH32V305CCT6
designator U?
RISC-V MCU, 144MHz, USB_480M, 2*CAN, 3*SPI, 4*OPA
footprint LQFP48
pins: 1 OSC_IN/PD0 (io), 2 OSC_OUT/PD1 (io), 3 NRST (in), 4 PC0/ADC10 (io), 5 PC1/ADC11 (io), 6 PC2/ADC12 (io), 7 PC3/ADC13 (io), 8 VSSA (power), 9 VDDA (power), 10 PA0/WKUP/ADC0 (io), 11 PA1/ADC1 (io), 12 PA2/ADC2 (io), 13 PA3/ADC3 (io), 14 PA4/ADC4/DAC0 (io), 15 PA5/ADC5/DAC1 (io), 16 PA6/ADC6 (io), 17 PA7/ADC7 (io), 18 PC4/ADC14 (io), 19 PC5/ADC15 (io), 20 PB0/ADC8 (io), 21 PB1/ADC9 (io), 22 PB2 (io), 23 PB10 (io), 24 PB11 (io), 25 VDD_VIO_1 (power), 26 VSS_1 (power), 27 PB12 (io), 28 PB13 (io), 29 PB14 (io), 30 PB15 (io), 31 PC6 (io), 32 PA8 (io), 33 PA9 (io), 34 PA10 (io), 35 PA11/USB1DM (io), 36 PA12/USB1DP (io), 37 PA13/SWDIO (io), 38 PA14/SWCLK (io), 39 PA15 (io), 40 PB3 (io), 41 PB4 (io), 42 PB5 (io), 43 PB6/USB2DM (io), 44 PB7/USB2DP (io), 45 PB8 (io), 46 PB9 (io), 47 VSS_3 (power), 48 VDD_VIO_3 (power)

## CH32V305F
designator U?
RISC-V FPU HD-MCU, 144MHz, USB_480M, CAN, UART*2, SPI
footprint TSSOP20
pins: 1 RST# (in), 2 PA5/UART1_CTS/PA1 (no5V) (io), 3 PB10/UART3_TX/I2C2_SCL (io), 4 PB11/UART3_RX/I2C2_SDA (io), 5 PB12/SPI2_NSS/CAN2_RX (io), 6 PB13/SPI2_SCK/UART3_CTS/CAN2_TX (io), 7 PB14/SPI2_MISO/UART3_RTS (io), 8 PB15/SPI2_MOSI/UART1_TX (io), 9 PC6 (io), 10 PC7 (io), 11 PC8 (io), 12 PC9/PA8/UART1_RX (io), 13 PA9/UART1_RTS/PA13/SWDIO (io), 14 VDD33/VIO (power), 15 PA14/SWCLK (io), 16 PB6/USB2DM/UART1X_TX (io), 17 PB7/USB2DP/UART1X_RX (io), 18 VSS/GND (power), 19 OSC_IN/PD0 (io), 20 OSC_OUT/PD1 (io)

## CH32V305GBU6
designator U?
RISC-V MCU, 144MHz, USB_480M, CAN, UART*5, SPI*3, SDIO
footprint QFN28_4X4
pins: 0 VSS/GND (power), 1 OSC_IN/PD0 (io), 2 OSC_OUT/PD1 (io), 3 RST# (in), 4 PC2/UART7TX (io), 5 PC3/UART7RX (io), 6 VIO (power), 7 PA4/SPI1NSS/SPI3NSS1/PA1 (io), 8 PA5/SPI1SCK (io), 9 PA6/SPI1MISO (io), 10 PA7/SPI1MOSI (io), 11 PB10/UART3TX/I2C2SCL (io), 12 PB11/UART3RX/I2C2SDA (io), 13 PB12/SPI2NSS/CAN2RX (io), 14 PB13/SPI2SCK/UART3CTS/CAN2TX (io), 15 PB14/SPI2MISO/UART3RTS (io), 16 PB15/SPI2MOSI/UART1TX2 (io), 17 PC8/SD_D0 (io), 18 PA8/UART1RX2/PC9/SD_D1 (io), 19 PA13/SWDIO/UART3TX2 (io), 20 VSS/GND (power), 21 VDD33 (power), 22 PA14/SWCLK/UART3RX2 (io), 23 PC10/UART4TX/SPI3SCK1/SD_D2 (io), 24 PC11/UART4RX/SPI3MISO1/SD_D3 (io), 25 PC12/UART5TX/SPI3MOSI1/SD_CK (io), 26 PD2/UART5RX/SD_CMD (io), 27 PB6/USB2DM/UART1TX1 (io), 28 PB7/USB2DP/UART1RX1 (io)

## CH32V305R
designator U?
RISC-V FPU HD-MCU, 144MHz, USB_480M, USB OTG, 2*CAN, 4*OPA
footprint LQFP64M_10X10
pins: 1 VBAT (power), 2 PC13/TAMPER-RTC (io), 3 PC14/OSC32IN (io), 4 PC15/OSC32OUT (io), 5 OSC_IN/PD0 (io), 6 OSC_OUT/PD1 (io), 7 NRST (in), 8 PC0/ADC10 (io), 9 PC1/ADC11 (io), 10 PC2/ADC12 (io), 11 PC3/ADC13 (io), 12 VSSA (power), 13 VDDA (power), 14 PA0/WKUP/ADC0 (io), 15 PA1/ADC1 (io), 16 PA2/ADC2 (io), 17 PA3/ADC3 (io), 18 VSS_4 (power), 19 VDD_4 (power), 20 PA4/ADC4/DAC0 (io), 21 PA5/ADC5/DAC1 (io), 22 PA6/ADC6 (io), 23 PA7/ADC7 (io), 24 PC4/ADC14 (io), 25 PC5/ADC15 (io), 26 PB0/ADC8 (io), 27 PB1/ADC9 (io), 28 PB2/BOOT1 (io), 29 PB10 (io), 30 PB11 (io), 31 VSS_1 (power), 32 VIO_1 (power), 33 PB12 (io), 34 PB13 (io), 35 PB14 (io), 36 PB15 (io), 37 PC6 (io), 38 PC7 (io), 39 PC8 (io), 40 PC9 (io), 41 PA8 (io), 42 PA9 (io), 43 PA10 (io), 44 PA11/USB1DM (io), 45 PA12/USB1DP (io), 46 PA13/SWDIO (io), 47 VSS_2 (power), 48 VDD_2 (power), 49 PA14/SWCLK (io), 50 PA15 (io), 51 PC10 (io), 52 PC11 (io), 53 PC12 (io), 54 PD2 (io), 55 PB3 (io), 56 PB4 (io), 57 PB5 (io), 58 PB6/USB2DM (io), 59 PB7/USB2DP (io), 60 BOOT0 (in), 61 PB8 (io), 62 PB9 (io), 63 VSS_3 (power), 64 VIO_3 (power)

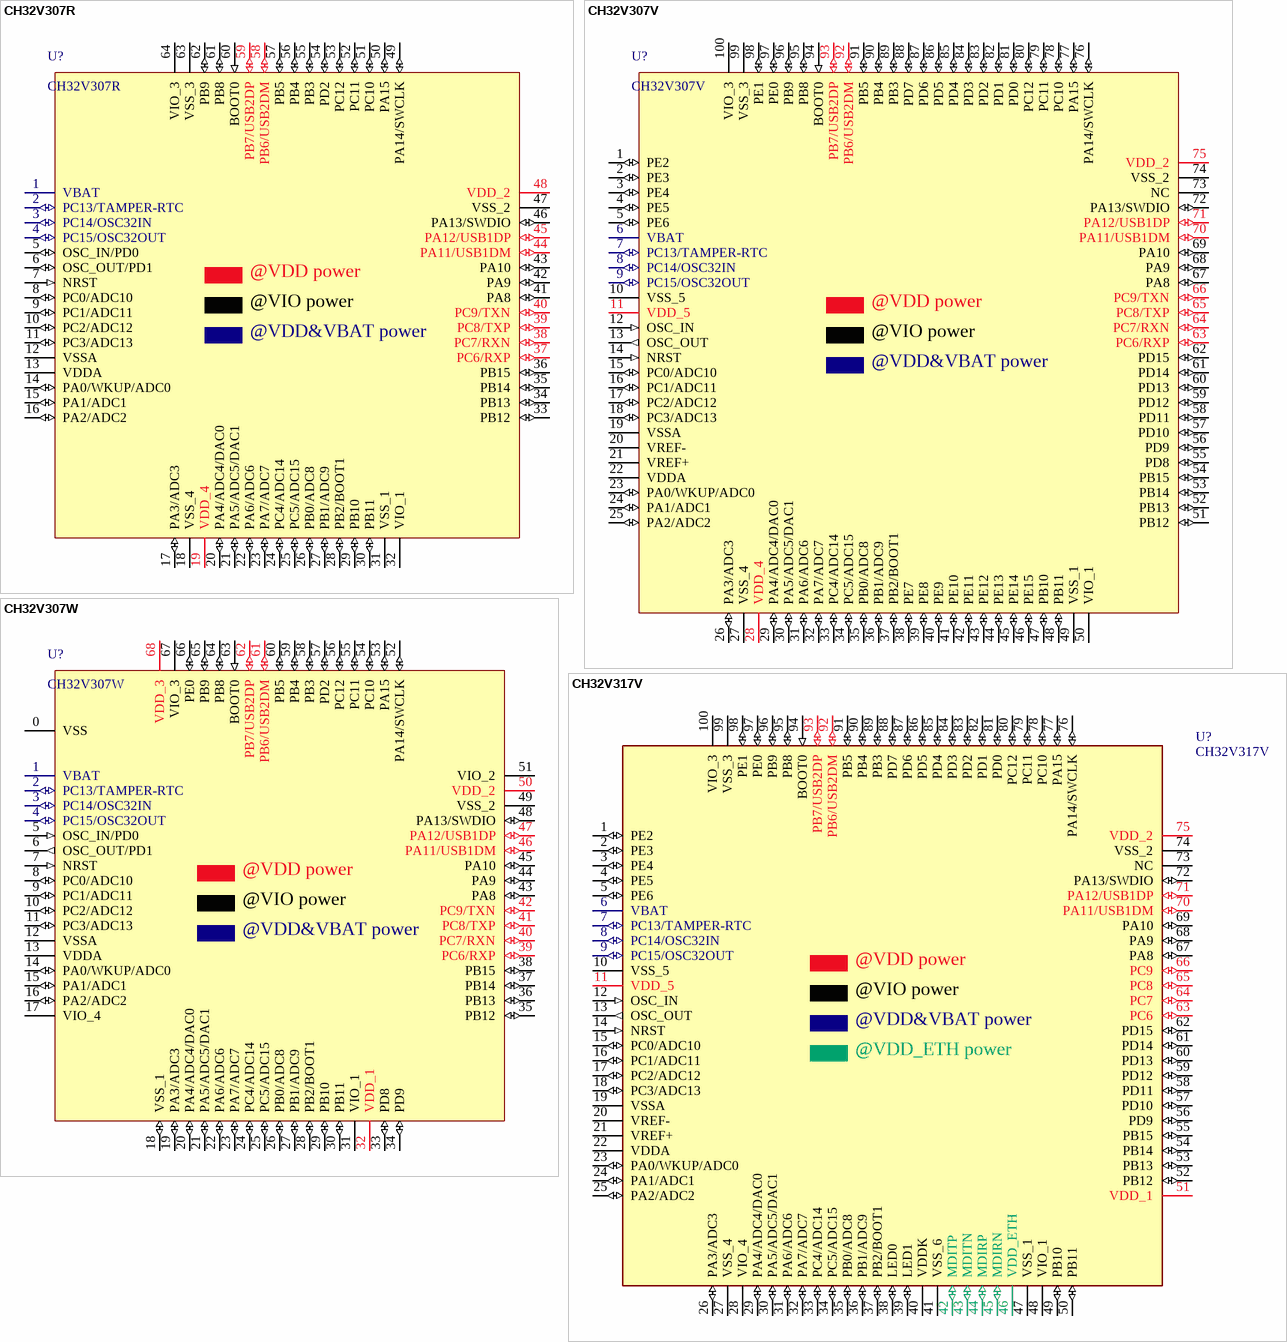
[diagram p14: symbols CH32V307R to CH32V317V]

## CH32V307R
designator U?
RISC-V FPU HD-MCU, 144MHz, USB_480M, USB OTG, 1000M Ethernet MAC, 2*CAN
footprint LQFP64M_10X10
pins: 1 VBAT (power), 2 PC13/TAMPER-RTC (io), 3 PC14/OSC32IN (io), 4 PC15/OSC32OUT (io), 5 OSC_IN/PD0 (io), 6 OSC_OUT/PD1 (io), 7 NRST (in), 8 PC0/ADC10 (io), 9 PC1/ADC11 (io), 10 PC2/ADC12 (io), 11 PC3/ADC13 (io), 12 VSSA (power), 13 VDDA (power), 14 PA0/WKUP/ADC0 (io), 15 PA1/ADC1 (io), 16 PA2/ADC2 (io), 17 PA3/ADC3 (io), 18 VSS_4 (power), 19 VDD_4 (power), 20 PA4/ADC4/DAC0 (io), 21 PA5/ADC5/DAC1 (io), 22 PA6/ADC6 (io), 23 PA7/ADC7 (io), 24 PC4/ADC14 (io), 25 PC5/ADC15 (io), 26 PB0/ADC8 (io), 27 PB1/ADC9 (io), 28 PB2/BOOT1 (io), 29 PB10 (io), 30 PB11 (io), 31 VSS_1 (power), 32 VIO_1 (power), 33 PB12 (io), 34 PB13 (io), 35 PB14 (io), 36 PB15 (io), 37 PC6/RXP (io), 38 PC7/RXN (io), 39 PC8/TXP (io), 40 PC9/TXN (io), 41 PA8 (io), 42 PA9 (io), 43 PA10 (io), 44 PA11/USB1DM (io), 45 PA12/USB1DP (io), 46 PA13/SWDIO (io), 47 VSS_2 (power), 48 VDD_2 (power), 49 PA14/SWCLK (io), 50 PA15 (io), 51 PC10 (io), 52 PC11 (io), 53 PC12 (io), 54 PD2 (io), 55 PB3 (io), 56 PB4 (io), 57 PB5 (io), 58 PB6/USB2DM (io), 59 PB7/USB2DP (io), 60 BOOT0 (in), 61 PB8 (io), 62 PB9 (io), 63 VSS_3 (power), 64 VIO_3 (power)

## CH32V307V
designator U?
RISC-V FPU HD-MCU, 144MHz, USB_480M, USB OTG, 1000M Ethernet MAC, 2*CAN, FSMC+DVP
footprint LQFP100
pins: 1 PE2 (io), 2 PE3 (io), 3 PE4 (io), 4 PE5 (io), 5 PE6 (io), 6 VBAT (power), 7 PC13/TAMPER-RTC (io), 8 PC14/OSC32IN (io), 9 PC15/OSC32OUT (io), 10 VSS_5 (power), 11 VDD_5 (power), 12 OSC_IN (in), 13 OSC_OUT (out), 14 NRST (in), 15 PC0/ADC10 (io), 16 PC1/ADC11 (io), 17 PC2/ADC12 (io), 18 PC3/ADC13 (io), 19 VSSA (power), 20 VREF- (power), 21 VREF+ (power), 22 VDDA (power), 23 PA0/WKUP/ADC0 (io), 24 PA1/ADC1 (io), 25 PA2/ADC2 (io), 26 PA3/ADC3 (io), 27 VSS_4 (power), 28 VDD_4 (power), 29 PA4/ADC4/DAC0 (io), 30 PA5/ADC5/DAC1 (io), 31 PA6/ADC6 (io), 32 PA7/ADC7 (io), 33 PC4/ADC14 (io), 34 PC5/ADC15 (io), 35 PB0/ADC8 (io), 36 PB1/ADC9 (io), 37 PB2/BOOT1 (io), 38 PE7 (io), 39 PE8 (io), 40 PE9 (io), 41 PE10 (io), 42 PE11 (io), 43 PE12 (io), 44 PE13 (io), 45 PE14 (io), 46 PE15 (io), 47 PB10 (io), 48 PB11 (io), 49 VSS_1 (power), 50 VIO_1 (power), 51 PB12 (io), 52 PB13 (io), 53 PB14 (io), 54 PB15 (io), 55 PD8 (io), 56 PD9 (io), 57 PD10 (io), 58 PD11 (io), 59 PD12 (io), 60 PD13 (io), 61 PD14 (io), 62 PD15 (io), 63 PC6/RXP (io), 64 PC7/RXN (io), 65 PC8/TXP (io), 66 PC9/TXN (io), 67 PA8 (io), 68 PA9 (io), 69 PA10 (io), 70 PA11/USB1DM (io), 71 PA12/USB1DP (io), 72 PA13/SWDIO (io), 73 NC (hiz), 74 VSS_2 (power), 75 VDD_2 (power), 76 PA14/SWCLK (io), 77 PA15 (io), 78 PC10 (io), 79 PC11 (io), 80 PC12 (io), 81 PD0 (io), 82 PD1 (io), 83 PD2 (io), 84 PD3 (io), 85 PD4 (io), 86 PD5 (io), 87 PD6 (io), 88 PD7 (io), 89 PB3 (io), 90 PB4 (io), 91 PB5 (io), 92 PB6/USB2DM (io), 93 PB7/USB2DP (io), 94 BOOT0 (in), 95 PB8 (io), 96 PB9 (io), 97 PE0 (io), 98 PE1 (io), 99 VSS_3 (power), 100 VIO_3 (power)

## CH32V307W
designator U?
RISC-V FPU HD-MCU, 144MHz, USB_480M, USB OTG, 1000M Ethernet MAC, 2*CAN
footprint QFN68_8X8
pins: 0 VSS (power), 1 VBAT (power), 2 PC13/TAMPER-RTC (io), 3 PC14/OSC32IN (io), 4 PC15/OSC32OUT (io), 5 OSC_IN/PD0 (in), 6 OSC_OUT/PD1 (out), 7 NRST (in), 8 PC0/ADC10 (io), 9 PC1/ADC11 (io), 10 PC2/ADC12 (io), 11 PC3/ADC13 (io), 12 VSSA (power), 13 VDDA (power), 14 PA0/WKUP/ADC0 (io), 15 PA1/ADC1 (io), 16 PA2/ADC2 (io), 17 VIO_4 (power), 18 VSS_1 (io), 19 PA3/ADC3 (io), 20 PA4/ADC4/DAC0 (io), 21 PA5/ADC5/DAC1 (io), 22 PA6/ADC6 (io), 23 PA7/ADC7 (io), 24 PC4/ADC14 (io), 25 PC5/ADC15 (io), 26 PB0/ADC8 (io), 27 PB1/ADC9 (io), 28 PB2/BOOT1 (io), 29 PB10 (io), 30 PB11 (io), 31 VIO_1 (power), 32 VDD_1 (power), 33 PD8 (io), 34 PD9 (io), 35 PB12 (io), 36 PB13 (io), 37 PB14 (io), 38 PB15 (io), 39 PC6/RXP (io), 40 PC7/RXN (io), 41 PC8/TXP (io), 42 PC9/TXN (io), 43 PA8 (io), 44 PA9 (io), 45 PA10 (io), 46 PA11/USB1DM (io), 47 PA12/USB1DP (io), 48 PA13/SWDIO (io), 49 VSS_2 (power), 50 VDD_2 (power), 51 VIO_2 (power), 52 PA14/SWCLK (io), 53 PA15 (io), 54 PC10 (io), 55 PC11 (io), 56 PC12 (io), 57 PD2 (io), 58 PB3 (io), 59 PB4 (io), 60 PB5 (io), 61 PB6/USB2DM (io), 62 PB7/USB2DP (io), 63 BOOT0 (in), 64 PB8 (io), 65 PB9 (io), 66 PE0 (io), 67 VIO_3 (power), 68 VDD_3 (power)

## CH32V317V
designator U?
RISC-V FPU HD-MCU, 144MHz, USB_480M, USB OTG, 100M Ethernet & Phy, 2*CAN, DVP
footprint LQFP100
pins: 1 PE2 (io), 2 PE3 (io), 3 PE4 (io), 4 PE5 (io), 5 PE6 (io), 6 VBAT (power), 7 PC13/TAMPER-RTC (io), 8 PC14/OSC32IN (io), 9 PC15/OSC32OUT (io), 10 VSS_5 (power), 11 VDD_5 (power), 12 OSC_IN (in), 13 OSC_OUT (out), 14 NRST (in), 15 PC0/ADC10 (io), 16 PC1/ADC11 (io), 17 PC2/ADC12 (io), 18 PC3/ADC13 (io), 19 VSSA (power), 20 VREF- (power), 21 VREF+ (power), 22 VDDA (power), 23 PA0/WKUP/ADC0 (io), 24 PA1/ADC1 (io), 25 PA2/ADC2 (io), 26 PA3/ADC3 (io), 27 VSS_4 (power), 28 VIO_4 (power), 29 PA4/ADC4/DAC0 (io), 30 PA5/ADC5/DAC1 (io), 31 PA6/ADC6 (io), 32 PA7/ADC7 (io), 33 PC4/ADC14 (io), 34 PC5/ADC15 (io), 35 PB0/ADC8 (io), 36 PB1/ADC9 (io), 37 PB2/BOOT1 (io), 38 LED0 (io), 39 LED1 (io), 40 VDDK (power), 41 VSS_6 (power), 42 MDITP (io), 43 MDITN (io), 44 MDIRP (io), 45 MDIRN (io), 46 VDD_ETH (power), 47 VSS_1 (power), 48 VIO_1 (power), 49 PB10 (io), 50 PB11 (io), 51 VDD_1 (power), 52 PB12 (io), 53 PB13 (io), 54 PB14 (io), 55 PB15 (io), 56 PD9 (io), 57 PD10 (io), 58 PD11 (io), 59 PD12 (io), 60 PD13 (io), 61 PD14 (io), 62 PD15 (io), 63 PC6 (io), 64 PC7 (io), 65 PC8 (io), 66 PC9 (io), 67 PA8 (io), 68 PA9 (io), 69 PA10 (io), 70 PA11/USB1DM (io), 71 PA12/USB1DP (io), 72 PA13/SWDIO (io), 73 NC (hiz), 74 VSS_2 (power), 75 VDD_2 (power), 76 PA14/SWCLK (io), 77 PA15 (io), 78 PC10 (io), 79 PC11 (io), 80 PC12 (io), 81 PD0 (io), 82 PD1 (io), 83 PD2 (io), 84 PD3 (io), 85 PD4 (io), 86 PD5 (io), 87 PD6 (io), 88 PD7 (io), 89 PB3 (io), 90 PB4 (io), 91 PB5 (io), 92 PB6/USB2DM (io), 93 PB7/USB2DP (io), 94 BOOT0 (in), 95 PB8 (io), 96 PB9 (io), 97 PE0 (io), 98 PE1 (io), 99 VSS_3 (power), 100 VIO_3 (power)

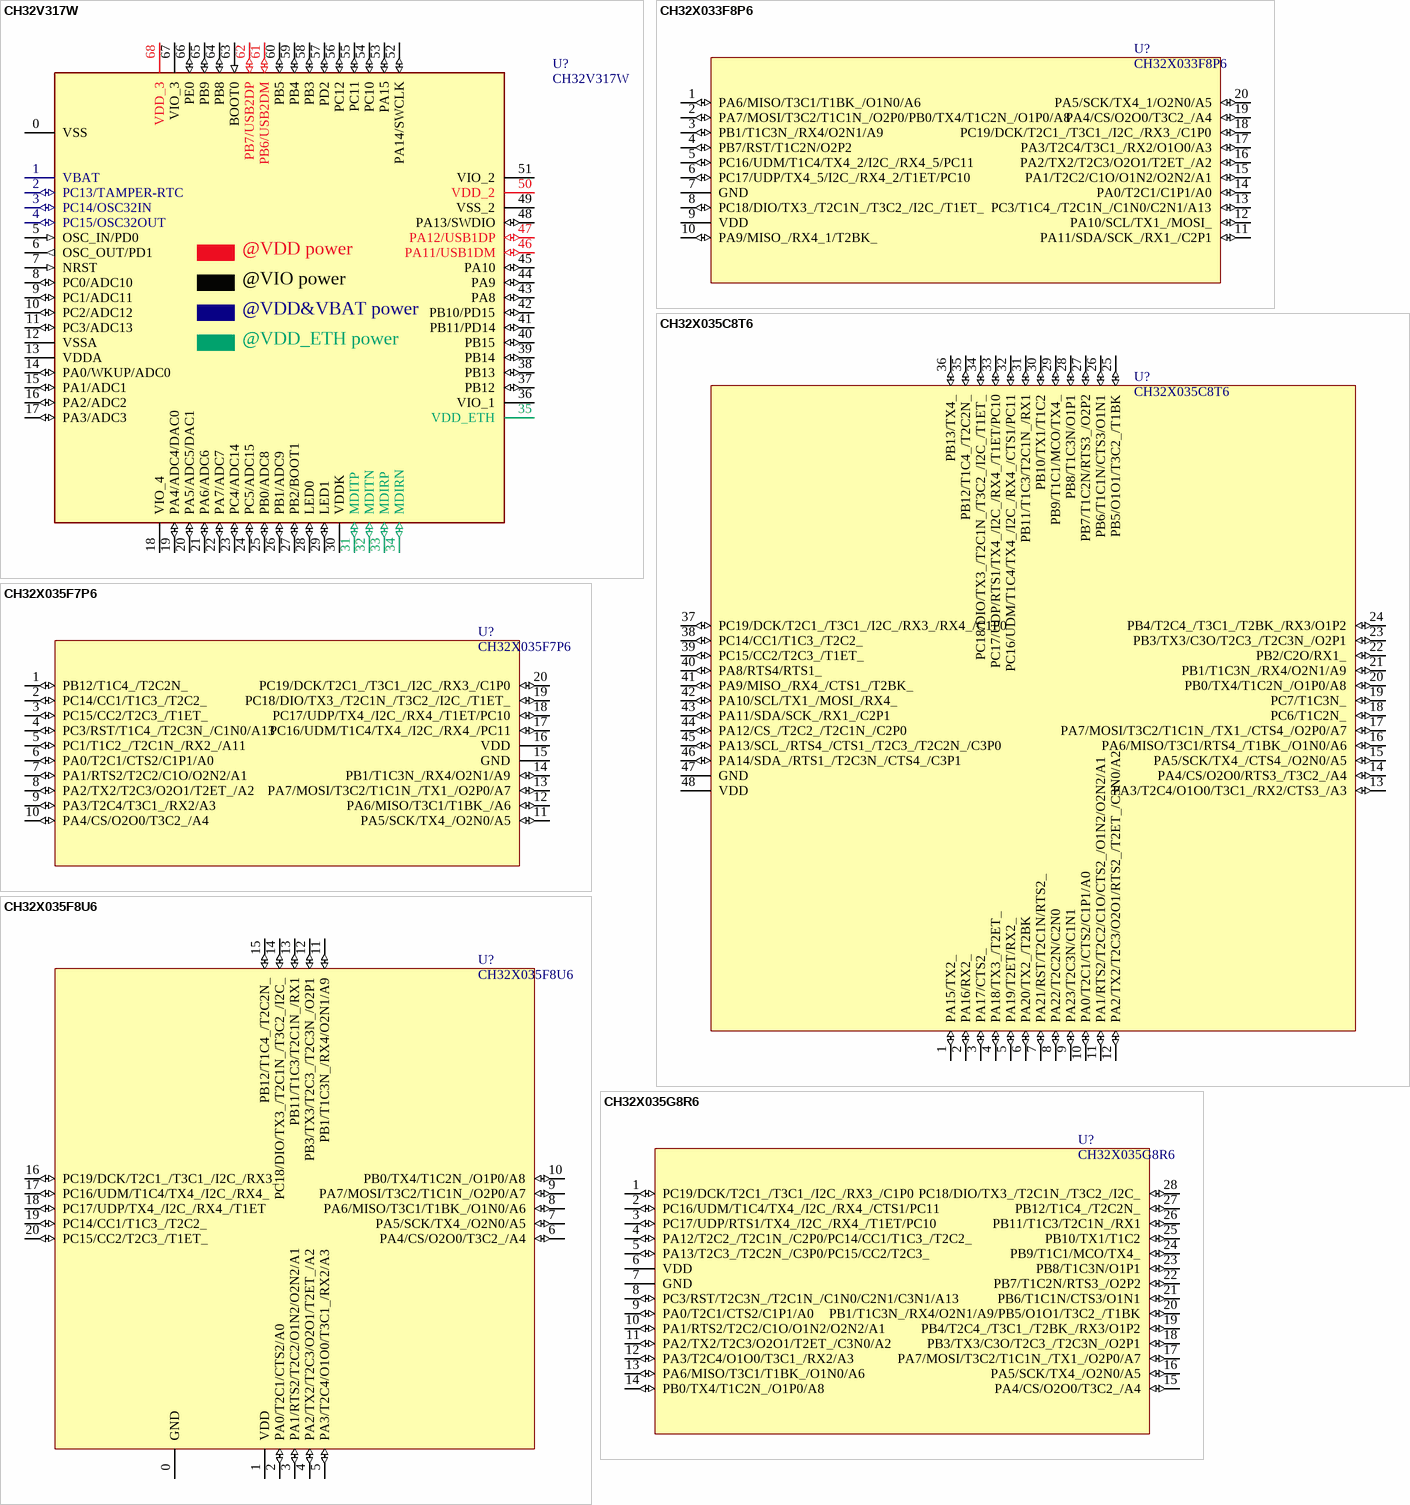
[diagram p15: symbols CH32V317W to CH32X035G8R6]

## CH32V317W
designator U?
RISC-V FPU HD-MCU, 144MHz, USB_480M, USB OTG, 100M Ethernet & Phy, 2*CAN
footprint QFN68_8X8
pins: 0 VSS (power), 1 VBAT (power), 2 PC13/TAMPER-RTC (io), 3 PC14/OSC32IN (io), 4 PC15/OSC32OUT (io), 5 OSC_IN/PD0 (in), 6 OSC_OUT/PD1 (out), 7 NRST (in), 8 PC0/ADC10 (io), 9 PC1/ADC11 (io), 10 PC2/ADC12 (io), 11 PC3/ADC13 (io), 12 VSSA (power), 13 VDDA (power), 14 PA0/WKUP/ADC0 (io), 15 PA1/ADC1 (io), 16 PA2/ADC2 (io), 17 PA3/ADC3 (io), 18 VIO_4 (power), 19 PA4/ADC4/DAC0 (io), 20 PA5/ADC5/DAC1 (io), 21 PA6/ADC6 (io), 22 PA7/ADC7 (io), 23 PC4/ADC14 (io), 24 PC5/ADC15 (io), 25 PB0/ADC8 (io), 26 PB1/ADC9 (io), 27 PB2/BOOT1 (io), 28 LED0 (io), 29 LED1 (io), 30 VDDK (power), 31 MDITP (io), 32 MDITN (io), 33 MDIRP (io), 34 MDIRN (io), 35 VDD_ETH (power), 36 VIO_1 (power), 37 PB12 (io), 38 PB13 (io), 39 PB14 (io), 40 PB15 (io), 41 PB11/PD14 (io), 42 PB10/PD15 (io), 43 PA8 (io), 44 PA9 (io), 45 PA10 (io), 46 PA11/USB1DM (io), 47 PA12/USB1DP (io), 48 PA13/SWDIO (io), 49 VSS_2 (power), 50 VDD_2 (power), 51 VIO_2 (power), 52 PA14/SWCLK (io), 53 PA15 (io), 54 PC10 (io), 55 PC11 (io), 56 PC12 (io), 57 PD2 (io), 58 PB3 (io), 59 PB4 (io), 60 PB5 (io), 61 PB6/USB2DM (io), 62 PB7/USB2DP (io), 63 BOOT0 (in), 64 PB8 (io), 65 PB9 (io), 66 PE0 (io), 67 VIO_3 (power), 68 VDD_3 (power)

## CH32X033F8P6
designator U?
RISC-V MCU with USB/ADC/SPI/I2C/UART*4/OA*2/CMP*2
footprint TSSOP20 (Footprint not found)
pins: 1 PA6/MISO/T3C1/T1BK_/O1N0/A6 (io), 2 PA7/MOSI/T3C2/T1C1N_/O2P0/PB0/TX4/T1C2N_/O1P0/A8 (io), 3 PB1/T1C3N_/RX4/O2N1/A9 (io), 4 PB7/RST/T1C2N/O2P2 (io), 5 PC16/UDM/T1C4/TX4_2/I2C_/RX4_5/PC11 (io), 6 PC17/UDP/TX4_5/I2C_/RX4_2/T1ET/PC10 (io), 7 GND (power), 8 PC18/DIO/TX3_/T2C1N_/T3C2_/I2C_/T1ET_ (io), 9 VDD (power), 10 PA9/MISO_/RX4_1/T2BK_ (io), 11 PA11/SDA/SCK_/RX1_/C2P1 (io), 12 PA10/SCL/TX1_/MOSI_ (io), 13 PC3/T1C4_/T2C1N_/C1N0/C2N1/A13 (io), 14 PA0/T2C1/C1P1/A0 (io), 15 PA1/T2C2/C1O/O1N2/O2N2/A1 (io), 16 PA2/TX2/T2C3/O2O1/T2ET_/A2 (io), 17 PA3/T2C4/T3C1_/RX2/O1O0/A3 (io), 18 PC19/DCK/T2C1_/T3C1_/I2C_/RX3_/C1P0 (io), 19 PA4/CS/O2O0/T3C2_/A4 (io), 20 PA5/SCK/TX4_1/O2N0/A5 (io)

## CH32X035C8T6
designator U?
RISC-V MCU with USB/PD/ADC/SPI/I2C/UART/OA/CMP
footprint LQFP48 (Footprint not found)
pins: 1 PA15/TX2_ (io), 2 PA16/RX2_ (io), 3 PA17/CTS2_ (io), 4 PA18/TX3_/T2ET_ (io), 5 PA19/T2ET/RX2_ (io), 6 PA20/TX2_/T2BK (io), 7 PA21/RST/T2C1N/RTS2_ (io), 8 PA22/T2C2N/C2N0 (io), 9 PA23/T2C3N/C1N1 (io), 10 PA0/T2C1/CTS2/C1P1/A0 (io), 11 PA1/RTS2/T2C2/C1O/CTS2_/O1N2/O2N2/A1 (io), 12 PA2/TX2/T2C3/O2O1/RTS2_/T2ET_/C3N0/A2 (io), 13 PA3/T2C4/O1O0/T3C1_/RX2/CTS3_/A3 (io), 14 PA4/CS/O2O0/RTS3_/T3C2_/A4 (io), 15 PA5/SCK/TX4_/CTS4_/O2N0/A5 (io), 16 PA6/MISO/T3C1/RTS4_/T1BK_/O1N0/A6 (io), 17 PA7/MOSI/T3C2/T1C1N_/TX1_/CTS4_/O2P0/A7 (io), 18 PC6/T1C2N_ (io), 19 PC7/T1C3N_ (io), 20 PB0/TX4/T1C2N_/O1P0/A8 (io), 21 PB1/T1C3N_/RX4/O2N1/A9 (io), 22 PB2/C2O/RX1_ (io), 23 PB3/TX3/C3O/T2C3_/T2C3N_/O2P1 (io), 24 PB4/T2C4_/T3C1_/T2BK_/RX3/O1P2 (io), 25 PB5/O1O1/T3C2_/T1BK (io), 26 PB6/T1C1N/CTS3/O1N1 (io), 27 PB7/T1C2N/RTS3_/O2P2 (io), 28 PB8/T1C3N/O1P1 (io), 29 PB9/T1C1/MCO/TX4_ (io), 30 PB10/TX1/T1C2 (io), 31 PB11/T1C3/T2C1N_/RX1 (io), 32 PC16/UDM/T1C4/TX4_/I2C_/RX4_/CTS1/PC11 (io), 33 PC17/UDP/RTS1/TX4_/I2C_/RX4_/T1ET/PC10 (io), 34 PC18/DIO/TX3_/T2C1N_/T3C2_/I2C_/T1ET_ (io), 35 PB12/T1C4_/T2C2N_ (io), 36 PB13/TX4_ (io), 37 PC19/DCK/T2C1_/T3C1_/I2C_/RX3_/RX4_/C1P0 (io), 38 PC14/CC1/T1C3_/T2C2_ (io), 39 PC15/CC2/T2C3_/T1ET_ (io), 40 PA8/RTS4/RTS1_ (io), 41 PA9/MISO_/RX4_/CTS1_/T2BK_ (io), 42 PA10/SCL/TX1_/MOSI_/RX4_ (io), 43 PA11/SDA/SCK_/RX1_/C2P1 (io), 44 PA12/CS_/T2C2_/T2C1N_/C2P0 (io), 45 PA13/SCL_/RTS4_/CTS1_/T2C3_/T2C2N_/C3P0 (io), 46 PA14/SDA_/RTS1_/T2C3N_/CTS4_/C3P1 (io), 47 GND (power), 48 VDD (power)

## CH32X035F7P6
designator U?
RISC-V MCU with USB/PD/ADC/SPI/I2C/UART/OA/CMP
footprint TSSOP20 (Footprint not found)
pins: 1 PB12/T1C4_/T2C2N_ (io), 2 PC14/CC1/T1C3_/T2C2_ (io), 3 PC15/CC2/T2C3_/T1ET_ (io), 4 PC3/RST/T1C4_/T2C3N_/C1N0/A13 (io), 5 PC1/T1C2_/T2C1N_/RX2_/A11 (io), 6 PA0/T2C1/CTS2/C1P1/A0 (io), 7 PA1/RTS2/T2C2/C1O/O2N2/A1 (io), 8 PA2/TX2/T2C3/O2O1/T2ET_/A2 (io), 9 PA3/T2C4/T3C1_/RX2/A3 (io), 10 PA4/CS/O2O0/T3C2_/A4 (io), 11 PA5/SCK/TX4_/O2N0/A5 (io), 12 PA6/MISO/T3C1/T1BK_/A6 (io), 13 PA7/MOSI/T3C2/T1C1N_/TX1_/O2P0/A7 (io), 14 PB1/T1C3N_/RX4/O2N1/A9 (io), 15 GND (power), 16 VDD (power), 17 PC16/UDM/T1C4/TX4_/I2C_/RX4_/PC11 (io), 18 PC17/UDP/TX4_/I2C_/RX4_/T1ET/PC10 (io), 19 PC18/DIO/TX3_/T2C1N_/T3C2_/I2C_/T1ET_ (io), 20 PC19/DCK/T2C1_/T3C1_/I2C_/RX3_/C1P0 (io)

## CH32X035F8U6
designator U?
RISC-V MCU with USB/PD/ADC/SPI/I2C/UART/OA
footprint QFN20_3X3
pins: 0 GND (power), 1 VDD (power), 2 PA0/T2C1/CTS2/A0 (io), 3 PA1/RTS2/T2C2/O1N2/O2N2/A1 (io), 4 PA2/TX2/T2C3/O2O1/T2ET_/A2 (io), 5 PA3/T2C4/O1O0/T3C1_/RX2/A3 (io), 6 PA4/CS/O2O0/T3C2_/A4 (io), 7 PA5/SCK/TX4_/O2N0/A5 (io), 8 PA6/MISO/T3C1/T1BK_/O1N0/A6 (io), 9 PA7/MOSI/T3C2/T1C1N_/O2P0/A7 (io), 10 PB0/TX4/T1C2N_/O1P0/A8 (io), 11 PB1/T1C3N_/RX4/O2N1/A9 (io), 12 PB3/TX3/T2C3_/T2C3N_/O2P1 (io), 13 PB11/T1C3/T2C1N_/RX1 (io), 14 PC18/DIO/TX3_/T2C1N_/T3C2_/I2C_ (io), 15 PB12/T1C4_/T2C2N_ (io), 16 PC19/DCK/T2C1_/T3C1_/I2C_/RX3_ (io), 17 PC16/UDM/T1C4/TX4_/I2C_/RX4_ (io), 18 PC17/UDP/TX4_/I2C_/RX4_/T1ET (io), 19 PC14/CC1/T1C3_/T2C2_ (io), 20 PC15/CC2/T2C3_/T1ET_ (io)

## CH32X035G8R6
designator U?
RISC-V MCU with USB/PD/ADC/SPI/I2C/UART/OA/CMP
footprint QSOP28 (Footprint not found)
pins: 1 PC19/DCK/T2C1_/T3C1_/I2C_/RX3_/C1P0 (io), 2 PC16/UDM/T1C4/TX4_/I2C_/RX4_/CTS1/PC11 (io), 3 PC17/UDP/RTS1/TX4_/I2C_/RX4_/T1ET/PC10 (io), 4 PA12/T2C2_/T2C1N_/C2P0/PC14/CC1/T1C3_/T2C2_ (io), 5 PA13/T2C3_/T2C2N_/C3P0/PC15/CC2/T2C3_ (io), 6 VDD (power), 7 GND (power), 8 PC3/RST/T2C3N_/T2C1N_/C1N0/C2N1/C3N1/A13 (io), 9 PA0/T2C1/CTS2/C1P1/A0 (io), 10 PA1/RTS2/T2C2/C1O/O1N2/O2N2/A1 (io), 11 PA2/TX2/T2C3/O2O1/T2ET_/C3N0/A2 (io), 12 PA3/T2C4/O1O0/T3C1_/RX2/A3 (io), 13 PA6/MISO/T3C1/T1BK_/O1N0/A6 (io), 14 PB0/TX4/T1C2N_/O1P0/A8 (io), 15 PA4/CS/O2O0/T3C2_/A4 (io), 16 PA5/SCK/TX4_/O2N0/A5 (io), 17 PA7/MOSI/T3C2/T1C1N_/TX1_/O2P0/A7 (io), 18 PB3/TX3/C3O/T2C3_/T2C3N_/O2P1 (io), 19 PB4/T2C4_/T3C1_/T2BK_/RX3/O1P2 (io), 20 PB1/T1C3N_/RX4/O2N1/A9/PB5/O1O1/T3C2_/T1BK (io), 21 PB6/T1C1N/CTS3/O1N1 (io), 22 PB7/T1C2N/RTS3_/O2P2 (io), 23 PB8/T1C3N/O1P1 (io), 24 PB9/T1C1/MCO/TX4_ (io), 25 PB10/TX1/T1C2 (io), 26 PB11/T1C3/T2C1N_/RX1 (io), 27 PB12/T1C4_/T2C2N_ (io), 28 PC18/DIO/TX3_/T2C1N_/T3C2_/I2C_ (io)

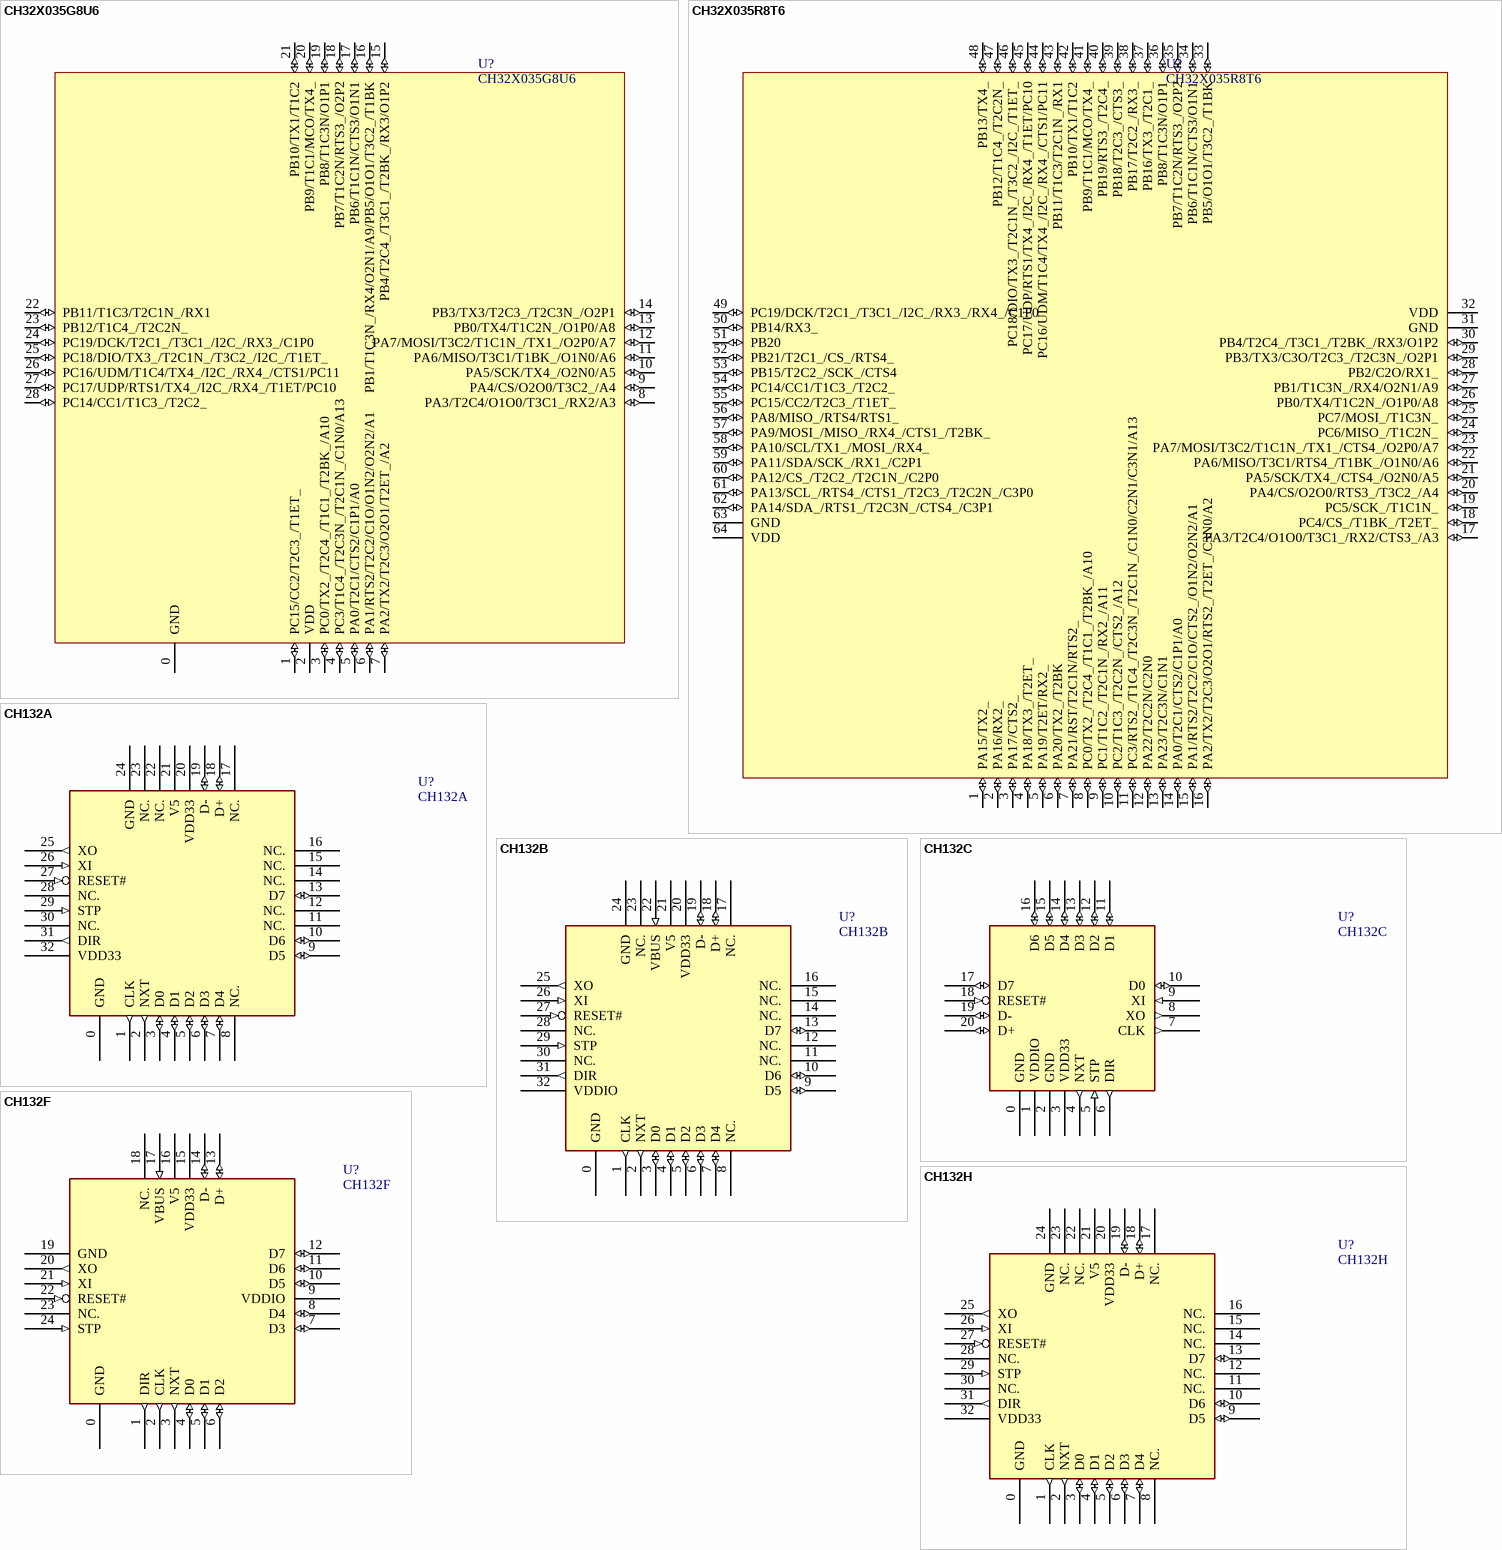
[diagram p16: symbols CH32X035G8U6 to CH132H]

## CH32X035G8U6
designator U?
RISC-V MCU with USB/PD/ADC/SPI/I2C/UART/OA/CMP
footprint QFN28_4X4 (Footprint not found)
pins: 0 GND (power), 1 PC15/CC2/T2C3_/T1ET_ (io), 2 VDD (power), 3 PC0/TX2_/T2C4_/T1C1_/T2BK_/A10 (io), 4 PC3/T1C4_/T2C3N_/T2C1N_/C1N0/A13 (io), 5 PA0/T2C1/CTS2/C1P1/A0 (io), 6 PA1/RTS2/T2C2/C1O/O1N2/O2N2/A1 (io), 7 PA2/TX2/T2C3/O2O1/T2ET_/A2 (io), 8 PA3/T2C4/O1O0/T3C1_/RX2/A3 (io), 9 PA4/CS/O2O0/T3C2_/A4 (io), 10 PA5/SCK/TX4_/O2N0/A5 (io), 11 PA6/MISO/T3C1/T1BK_/O1N0/A6 (io), 12 PA7/MOSI/T3C2/T1C1N_/TX1_/O2P0/A7 (io), 13 PB0/TX4/T1C2N_/O1P0/A8 (io), 14 PB3/TX3/T2C3_/T2C3N_/O2P1 (io), 15 PB4/T2C4_/T3C1_/T2BK_/RX3/O1P2 (io), 16 PB1/T1C3N_/RX4/O2N1/A9/PB5/O1O1/T3C2_/T1BK (io), 17 PB6/T1C1N/CTS3/O1N1 (io), 18 PB7/T1C2N/RTS3_/O2P2 (io), 19 PB8/T1C3N/O1P1 (io), 20 PB9/T1C1/MCO/TX4_ (io), 21 PB10/TX1/T1C2 (io), 22 PB11/T1C3/T2C1N_/RX1 (io), 23 PB12/T1C4_/T2C2N_ (io), 24 PC19/DCK/T2C1_/T3C1_/I2C_/RX3_/C1P0 (io), 25 PC18/DIO/TX3_/T2C1N_/T3C2_/I2C_/T1ET_ (io), 26 PC16/UDM/T1C4/TX4_/I2C_/RX4_/CTS1/PC11 (io), 27 PC17/UDP/RTS1/TX4_/I2C_/RX4_/T1ET/PC10 (io), 28 PC14/CC1/T1C3_/T2C2_ (io)

## CH32X035R8T6
designator U?
RISC-V MCU with USB/PD/ADC/SPI/I2C/UART/OA/CMP
footprint LQFP64M_10X10
pins: 1 PA15/TX2_ (io), 2 PA16/RX2_ (io), 3 PA17/CTS2_ (io), 4 PA18/TX3_/T2ET_ (io), 5 PA19/T2ET/RX2_ (io), 6 PA20/TX2_/T2BK (io), 7 PA21/RST/T2C1N/RTS2_ (io), 8 PC0/TX2_/T2C4_/T1C1_/T2BK_/A10 (io), 9 PC1/T1C2_/T2C1N_/RX2_/A11 (io), 10 PC2/T1C3_/T2C2N_/CTS2_/A12 (io), 11 PC3/RTS2_/T1C4_/T2C3N_/T2C1N_/C1N0/C2N1/C3N1/A13 (io), 12 PA22/T2C2N/C2N0 (io), 13 PA23/T2C3N/C1N1 (io), 14 PA0/T2C1/CTS2/C1P1/A0 (io), 15 PA1/RTS2/T2C2/C1O/CTS2_/O1N2/O2N2/A1 (io), 16 PA2/TX2/T2C3/O2O1/RTS2_/T2ET_/C3N0/A2 (io), 17 PA3/T2C4/O1O0/T3C1_/RX2/CTS3_/A3 (io), 18 PC4/CS_/T1BK_/T2ET_ (io), 19 PC5/SCK_/T1C1N_ (io), 20 PA4/CS/O2O0/RTS3_/T3C2_/A4 (io), 21 PA5/SCK/TX4_/CTS4_/O2N0/A5 (io), 22 PA6/MISO/T3C1/RTS4_/T1BK_/O1N0/A6 (io), 23 PA7/MOSI/T3C2/T1C1N_/TX1_/CTS4_/O2P0/A7 (io), 24 PC6/MISO_/T1C2N_ (io), 25 PC7/MOSI_/T1C3N_ (io), 26 PB0/TX4/T1C2N_/O1P0/A8 (io), 27 PB1/T1C3N_/RX4/O2N1/A9 (io), 28 PB2/C2O/RX1_ (io), 29 PB3/TX3/C3O/T2C3_/T2C3N_/O2P1 (io), 30 PB4/T2C4_/T3C1_/T2BK_/RX3/O1P2 (io), 31 GND (power), 32 VDD (power), 33 PB5/O1O1/T3C2_/T1BK (io), 34 PB6/T1C1N/CTS3/O1N1 (io), 35 PB7/T1C2N/RTS3_/O2P2 (io), 36 PB8/T1C3N/O1P1 (io), 37 PB16/TX3_/T2C1_ (io), 38 PB17/T2C2_/RX3_ (io), 39 PB18/T2C3_/CTS3_ (io), 40 PB19/RTS3_/T2C4_ (io), 41 PB9/T1C1/MCO/TX4_ (io), 42 PB10/TX1/T1C2 (io), 43 PB11/T1C3/T2C1N_/RX1 (io), 44 PC16/UDM/T1C4/TX4_/I2C_/RX4_/CTS1/PC11 (io), 45 PC17/UDP/RTS1/TX4_/I2C_/RX4_/T1ET/PC10 (io), 46 PC18/DIO/TX3_/T2C1N_/T3C2_/I2C_/T1ET_ (io), 47 PB12/T1C4_/T2C2N_ (io), 48 PB13/TX4_ (io), 49 PC19/DCK/T2C1_/T3C1_/I2C_/RX3_/RX4_/C1P0 (io), 50 PB14/RX3_ (io), 51 PB20 (io), 52 PB21/T2C1_/CS_/RTS4_ (io), 53 PB15/T2C2_/SCK_/CTS4 (io), 54 PC14/CC1/T1C3_/T2C2_ (io), 55 PC15/CC2/T2C3_/T1ET_ (io), 56 PA8/MISO_/RTS4/RTS1_ (io), 57 PA9/MOSI_/MISO_/RX4_/CTS1_/T2BK_ (io), 58 PA10/SCL/TX1_/MOSI_/RX4_ (io), 59 PA11/SDA/SCK_/RX1_/C2P1 (io), 60 PA12/CS_/T2C2_/T2C1N_/C2P0 (io), 61 PA13/SCL_/RTS4_/CTS1_/T2C3_/T2C2N_/C3P0 (io), 62 PA14/SDA_/RTS1_/T2C3N_/CTS4_/C3P1 (io), 63 GND (power), 64 VDD (power)

## CH132A
designator U?
ULPI High-Speed USB PHY (Transceiver)
footprint QFN32_5X5 (Footprint not found)
pins: 0 GND (power), 1 CLK (out), 2 NXT (out), 3 D0 (io), 4 D1 (io), 5 D2 (io), 6 D3 (io), 7 D4 (io), 8 NC., 9 D5 (io), 10 D6 (io), 11 NC., 12 NC., 13 D7 (io), 14 NC., 15 NC., 16 NC., 17 NC., 18 D+ (io), 19 D- (io), 20 VDD33 (power), 21 V5 (power), 22 NC., 23 NC., 24 GND (power), 25 XO (out), 26 XI (in), 27 RESET# (in), 28 NC., 29 STP (in), 30 NC., 31 DIR (out), 32 VDD33

## CH132B
designator U?
ULPI High-Speed USB PHY (Transceiver)
footprint QFN32_5X5
pins: 0 GND (power), 1 CLK (out), 2 NXT (out), 3 D0 (io), 4 D1 (io), 5 D2 (io), 6 D3 (io), 7 D4 (io), 8 NC., 9 D5 (io), 10 D6 (io), 11 NC., 12 NC., 13 D7 (io), 14 NC., 15 NC., 16 NC., 17 NC., 18 D+ (io), 19 D- (io), 20 VDD33 (power), 21 V5 (power), 22 VBUS (in), 23 NC., 24 GND (power), 25 XO (out), 26 XI (in), 27 RESET# (in), 28 NC., 29 STP (in), 30 NC., 31 DIR (out), 32 VDDIO

## CH132C
designator U?
ULPI High-Speed USB PHY (Transceiver)
footprint QFN20C_2X2 (Footprint not found)
pins: 0 GND (power), 1 VDDIO (power), 2 GND (power), 3 VDD33 (power), 4 NXT (out), 5 STP (in), 6 DIR (out), 7 CLK (out), 8 XO (out), 9 XI (in), 10 D0 (io), 11 D1 (io), 12 D2 (io), 13 D3 (io), 14 D4 (io), 15 D5 (io), 16 D6 (io), 17 D7 (io), 18 RESET# (in), 19 D- (io), 20 D+ (io)

## CH132F
designator U?
ULPI High-Speed USB PHY (Transceiver)
footprint QFN24_4X4
pins: 0 GND (power), 1 DIR (out), 2 CLK (out), 3 NXT (out), 4 D0 (io), 5 D1 (io), 6 D2 (io), 7 D3 (io), 8 D4 (io), 9 VDDIO (power), 10 D5 (io), 11 D6 (io), 12 D7 (io), 13 D+ (io), 14 D- (io), 15 VDD33 (power), 16 V5 (power), 17 VBUS (in), 18 NC., 19 GND (power), 20 XO (out), 21 XI (in), 22 RESET# (in), 23 NC., 24 STP (in)

## CH132H
designator U?
ULPI High-Speed USB PHY (Transceiver)
footprint QFN32_5X5 (Footprint not found)
pins: 0 GND (power), 1 CLK (out), 2 NXT (out), 3 D0 (io), 4 D1 (io), 5 D2 (io), 6 D3 (io), 7 D4 (io), 8 NC., 9 D5 (io), 10 D6 (io), 11 NC., 12 NC., 13 D7 (io), 14 NC., 15 NC., 16 NC., 17 NC., 18 D+ (io), 19 D- (io), 20 VDD33 (power), 21 V5 (power), 22 NC., 23 NC., 24 GND (power), 25 XO (out), 26 XI (in), 27 RESET# (in), 28 NC., 29 STP (in), 30 NC., 31 DIR (out), 32 VDD33 (power)

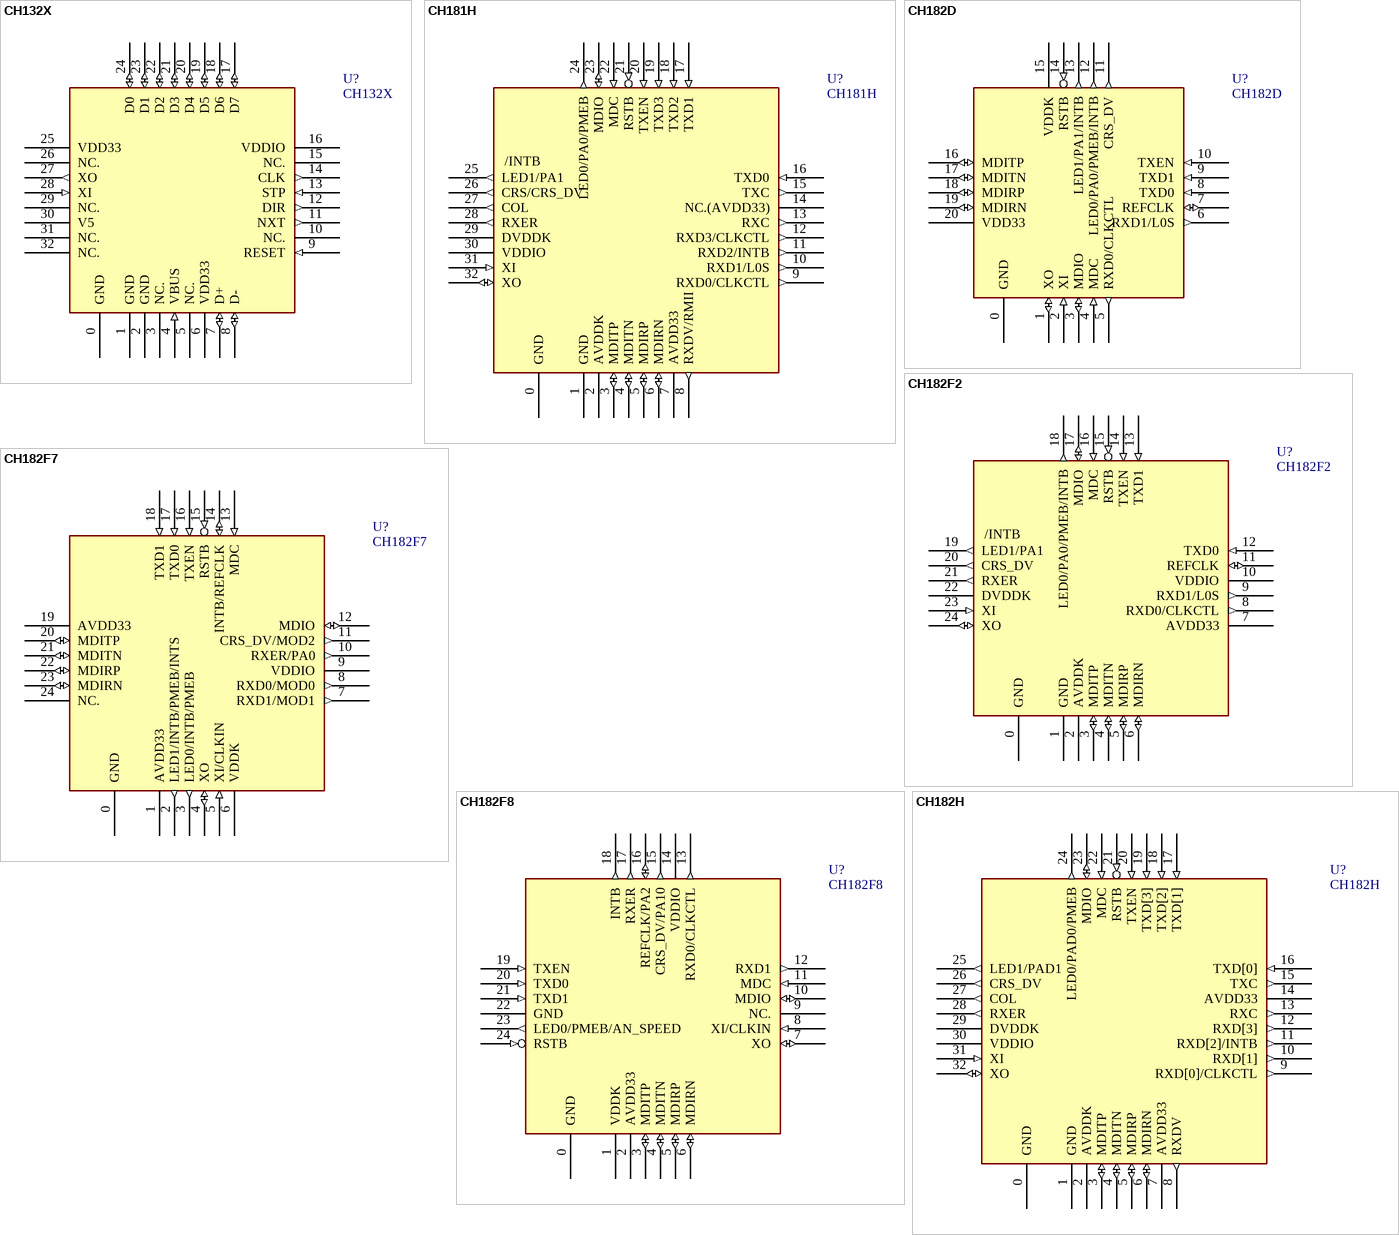
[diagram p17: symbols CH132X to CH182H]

## CH132X
designator U?
ULPI High-Speed USB PHY (Transceiver)
footprint QFN32_5X5
pins: 0 GND (power), 1 GND (power), 2 GND (power), 3 NC., 4 VBUS (in), 5 NC., 6 VDD33 (power), 7 D+ (io), 8 D- (io), 9 RESET (in), 10 NC., 11 NXT (out), 12 DIR (out), 13 STP (in), 14 CLK (out), 15 NC., 16 VDDIO (power), 17 D7 (io), 18 D6 (io), 19 D5 (io), 20 D4 (io), 21 D3 (io), 22 D2 (io), 23 D1 (io), 24 D0 (io), 25 VDD33 (power), 26 NC., 27 XO (out), 28 XI (in), 29 NC., 30 V5 (power), 31 NC., 32 NC.

## CH181H
designator U?
MII/RMII 10/100M Ethernet PHY (Transceiver) with auto MDIX
footprint QFN32_5X5
pins: 0 GND (power), 1 GND (power), 2 AVDDK (power), 3 MDITP (io), 4 MDITN (io), 5 MDIRP (io), 6 MDIRN (io), 7 AVDD33 (power), 8 RXDV/RMII (out), 9 RXD0/CLKCTL (out), 10 RXD1/L0S (out), 11 RXD2/INTB (out), 12 RXD3/CLKCTL (out), 13 RXC (out), 14 NC.(AVDD33) (power), 15 TXC (out), 16 TXD0 (in), 17 TXD1 (in), 18 TXD2 (in), 19 TXD3 (in), 20 TXEN (in), 21 RSTB (in), 22 MDC (in), 23 MDIO (io), 24 LED0/PA0/PMEB (out), 25 LED1/PA1 (out), 26 CRS/CRS_DV (out), 27 COL (out), 28 RXER (out), 29 DVDDK (power), 30 VDDIO (power), 31 XI (in), 32 XO (io)

## CH182D
designator U?
RMII 10/100M Ethernet PHY (Transceiver) with auto MDIX
footprint QFN20_3X3
pins: 0 GND (power), 1 XO (io), 2 XI (in), 3 MDIO (io), 4 MDC (in), 5 RXD0/CLKCTL (out), 6 RXD1/L0S (out), 7 REFCLK (io), 8 TXD0 (in), 9 TXD1 (in), 10 TXEN (in), 11 CRS_DV (out), 12 LED0/PA0/PMEB/INTB (out), 13 LED1/PA1/INTB (out), 14 RSTB (in), 15 VDDK (power), 16 MDITP (io), 17 MDITN (io), 18 MDIRP (io), 19 MDIRN (io), 20 VDD33 (power)

## CH182F2
designator U?
RMII 10/100M Ethernet PHY (Transceiver) with auto MDIX
footprint QFN24_4X4
pins: 0 GND (power), 1 GND (power), 2 AVDDK (power), 3 MDITP (io), 4 MDITN (io), 5 MDIRP (io), 6 MDIRN (io), 7 AVDD33 (power), 8 RXD0/CLKCTL (out), 9 RXD1/L0S (out), 10 VDDIO (power), 11 REFCLK (io), 12 TXD0 (in), 13 TXD1 (in), 14 TXEN (in), 15 RSTB (in), 16 MDC (in), 17 MDIO (io), 18 LED0/PA0/PMEB/INTB (out), 19 LED1/PA1 (out), 20 CRS_DV (out), 21 RXER (out), 22 DVDDK (power), 23 XI (in), 24 XO (io)

## CH182F7
designator U?
RMII 10/100M Ethernet PHY (Transceiver) with auto MDIX
footprint QFN24_4X4
pins: 0 GND (power), 1 AVDD33 (power), 2 LED1/INTB/PMEB/INTS (out), 3 LED0/INTB/PMEB (out), 4 XO (io), 5 XI/CLKIN (in), 6 VDDK (power), 7 RXD1/MOD1 (out), 8 RXD0/MOD0 (out), 9 VDDIO (power), 10 RXER/PA0 (out), 11 CRS_DV/MOD2 (out), 12 MDIO (io), 13 MDC (in), 14 INTB/REFCLK (io), 15 RSTB (in), 16 TXEN (in), 17 TXD0 (in), 18 TXD1 (in), 19 AVDD33 (power), 20 MDITP (io), 21 MDITN (io), 22 MDIRP (io), 23 MDIRN (io), 24 NC.

## CH182F8
designator U?
RMII 10/100M Ethernet PHY (Transceiver) with auto MDIX
footprint QFN24_4X4
pins: 0 GND (power), 1 VDDK (power), 2 AVDD33 (power), 3 MDITP (io), 4 MDITN (io), 5 MDIRP (io), 6 MDIRN (io), 7 XO (io), 8 XI/CLKIN (in), 9 NC., 10 MDIO (io), 11 MDC (in), 12 RXD1 (out), 13 RXD0/CLKCTL (out), 14 VDDIO (power), 15 CRS_DV/PA10 (out), 16 REFCLK/PA2 (io), 17 RXER (out), 18 INTB (out), 19 TXEN (in), 20 TXD0 (in), 21 TXD1 (in), 22 GND (power), 23 LED0/PMEB/AN_SPEED (out), 24 RSTB (in)

## CH182H
designator U?
MII/RMII 10/100M Ethernet PHY (Transceiver) with auto MDIX
footprint QFN32_5X5 (Footprint not found)
pins: 0 GND (power), 1 GND (power), 2 AVDDK (power), 3 MDITP (io), 4 MDITN (io), 5 MDIRP (io), 6 MDIRN (io), 7 AVDD33 (power), 8 RXDV (out), 9 RXD[0]/CLKCTL (out), 10 RXD[1] (out), 11 RXD[2]/INTB (out), 12 RXD[3] (out), 13 RXC (out), 14 AVDD33 (power), 15 TXC (out), 16 TXD[0] (in), 17 TXD[1] (in), 18 TXD[2] (in), 19 TXD[3] (in), 20 TXEN (in), 21 RSTB (in), 22 MDC (in), 23 MDIO (io), 24 LED0/PAD0/PMEB (out), 25 LED1/PAD1 (out), 26 CRS_DV (out), 27 COL (out), 28 RXER (out), 29 DVDDK (power), 30 VDDIO (power), 31 XI (in), 32 XO (io)

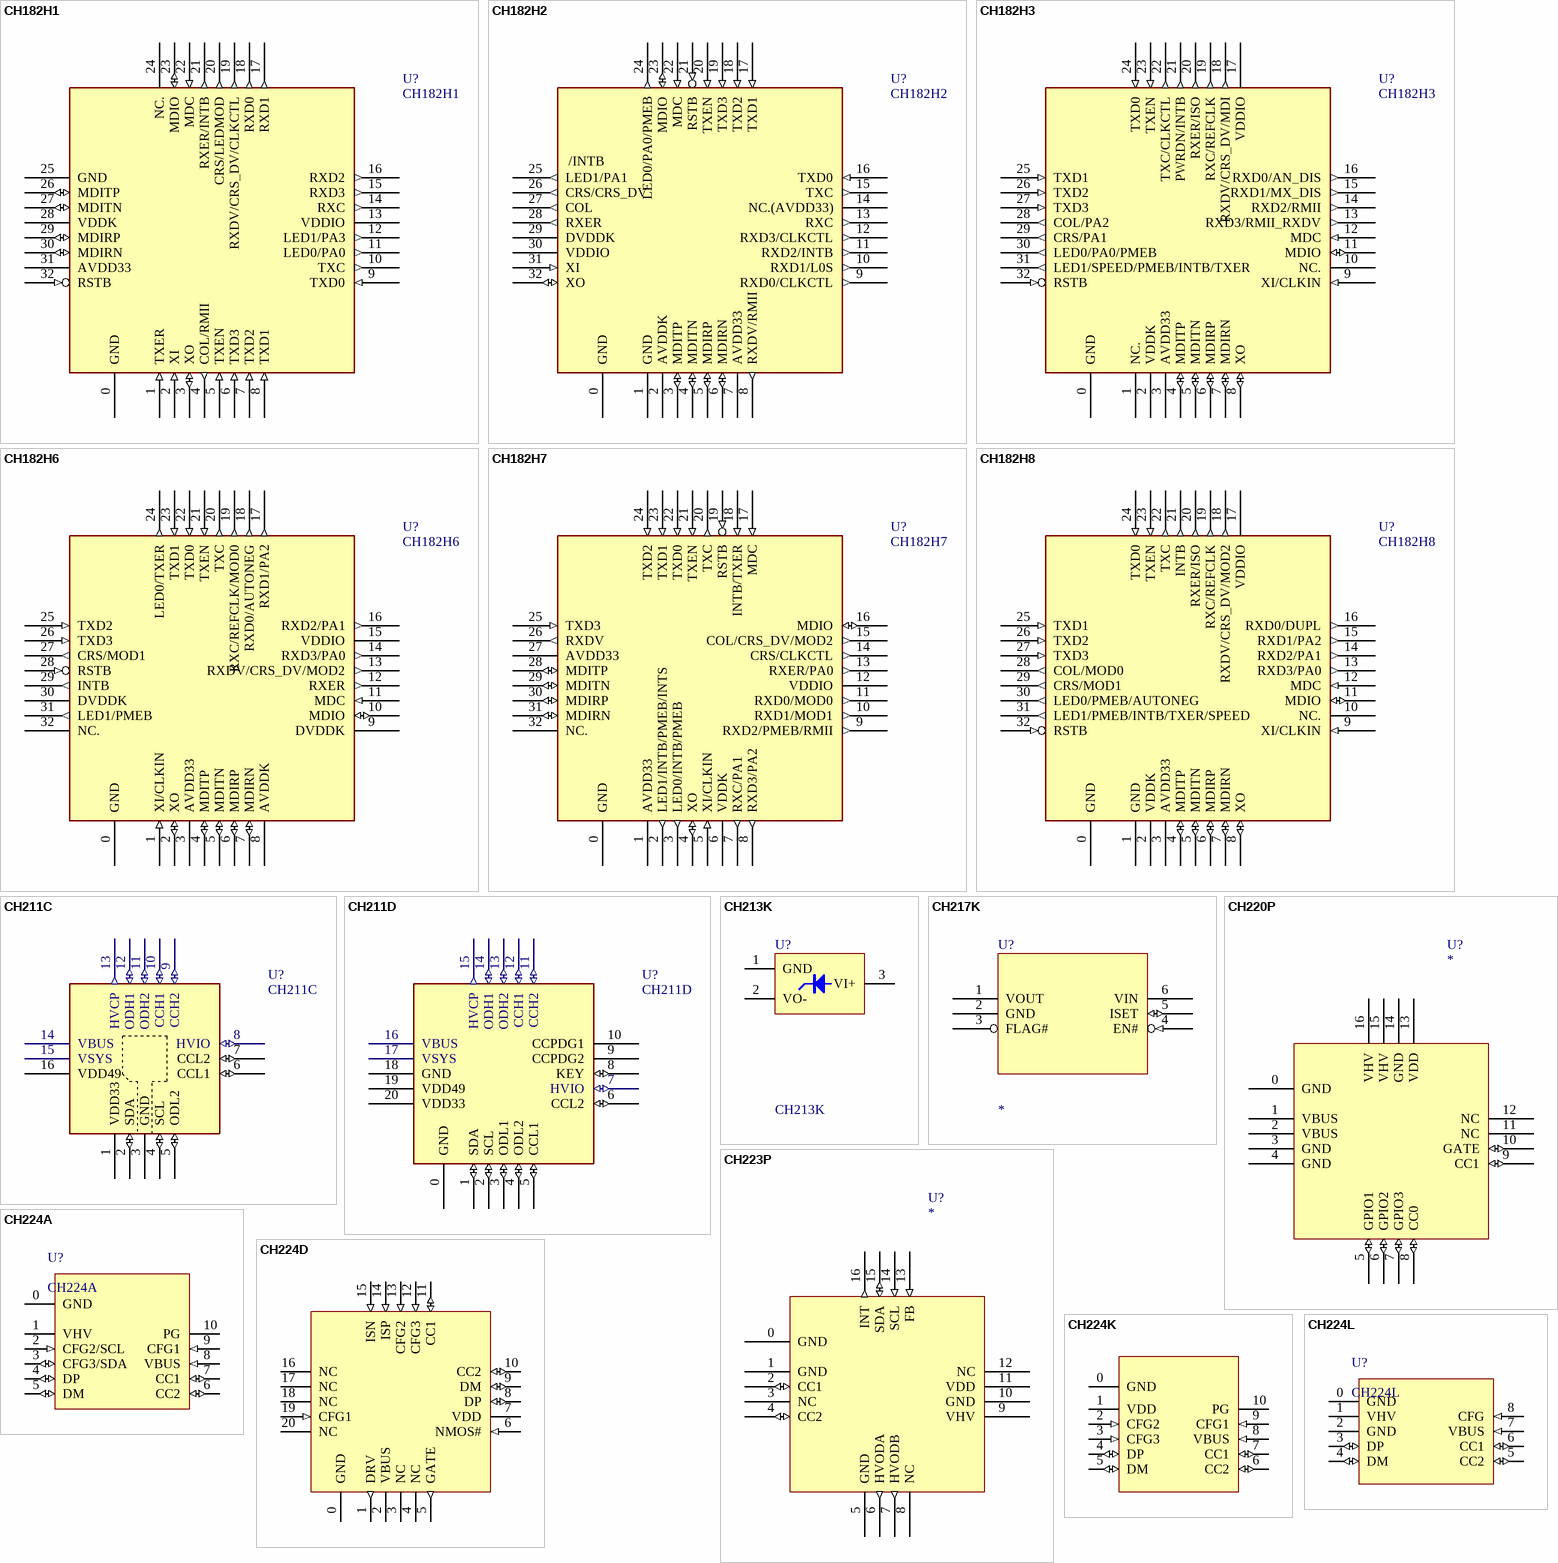
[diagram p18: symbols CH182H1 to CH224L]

## CH182H1
designator U?
MII/RMII 10/100M Ethernet PHY (Transceiver) with auto MDIX
footprint QFN32_4X4
pins: 0 GND (power), 1 TXER (in), 2 XI (in), 3 XO (io), 4 COL/RMII (out), 5 TXEN (in), 6 TXD3 (in), 7 TXD2 (in), 8 TXD1 (in), 9 TXD0 (in), 10 TXC (out), 11 LED0/PA0 (out), 12 LED1/PA3 (out), 13 VDDIO (power), 14 RXC (out), 15 RXD3 (out), 16 RXD2 (out), 17 RXD1 (out), 18 RXD0 (out), 19 RXDV/CRS_DV/CLKCTL (out), 20 CRS/LEDMOD (out), 21 RXER/INTB (out), 22 MDC (in), 23 MDIO (io), 24 NC., 25 GND (power), 26 MDITP (io), 27 MDITN (io), 28 VDDK (power), 29 MDIRP (io), 30 MDIRN (io), 31 AVDD33 (power), 32 RSTB (in)

## CH182H2
designator U?
MII/RMII 10/100M Ethernet PHY (Transceiver) with auto MDIX
footprint QFN32_5X5
pins: 0 GND (power), 1 GND (power), 2 AVDDK (power), 3 MDITP (io), 4 MDITN (io), 5 MDIRP (io), 6 MDIRN (io), 7 AVDD33 (power), 8 RXDV/RMII (out), 9 RXD0/CLKCTL (out), 10 RXD1/L0S (out), 11 RXD2/INTB (out), 12 RXD3/CLKCTL (out), 13 RXC (out), 14 NC.(AVDD33) (power), 15 TXC (out), 16 TXD0 (in), 17 TXD1 (in), 18 TXD2 (in), 19 TXD3 (in), 20 TXEN (in), 21 RSTB (in), 22 MDC (in), 23 MDIO (io), 24 LED0/PA0/PMEB (out), 25 LED1/PA1 (out), 26 CRS/CRS_DV (out), 27 COL (out), 28 RXER (out), 29 DVDDK (power), 30 VDDIO (power), 31 XI (in), 32 XO (io)

## CH182H3
designator U?
MII/RMII 10/100M Ethernet PHY (Transceiver) with auto MDIX
footprint QFN32_5X5
pins: 0 GND (power), 1 NC., 2 VDDK (power), 3 AVDD33 (power), 4 MDITP (io), 5 MDITN (io), 6 MDIRP (io), 7 MDIRN (io), 8 XO (io), 9 XI/CLKIN (in), 10 NC., 11 MDIO (io), 12 MDC (in), 13 RXD3/RMII_RXDV (out), 14 RXD2/RMII (out), 15 RXD1/MX_DIS (out), 16 RXD0/AN_DIS (out), 17 VDDIO (power), 18 RXDV/CRS_DV/MDI (out), 19 RXC/REFCLK (out), 20 RXER/ISO (out), 21 PWRDN/INTB (out), 22 TXC/CLKCTL (out), 23 TXEN (in), 24 TXD0 (in), 25 TXD1 (in), 26 TXD2 (in), 27 TXD3 (in), 28 COL/PA2 (out), 29 CRS/PA1 (out), 30 LED0/PA0/PMEB (out), 31 LED1/SPEED/PMEB/INTB/TXER (out), 32 RSTB (in)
